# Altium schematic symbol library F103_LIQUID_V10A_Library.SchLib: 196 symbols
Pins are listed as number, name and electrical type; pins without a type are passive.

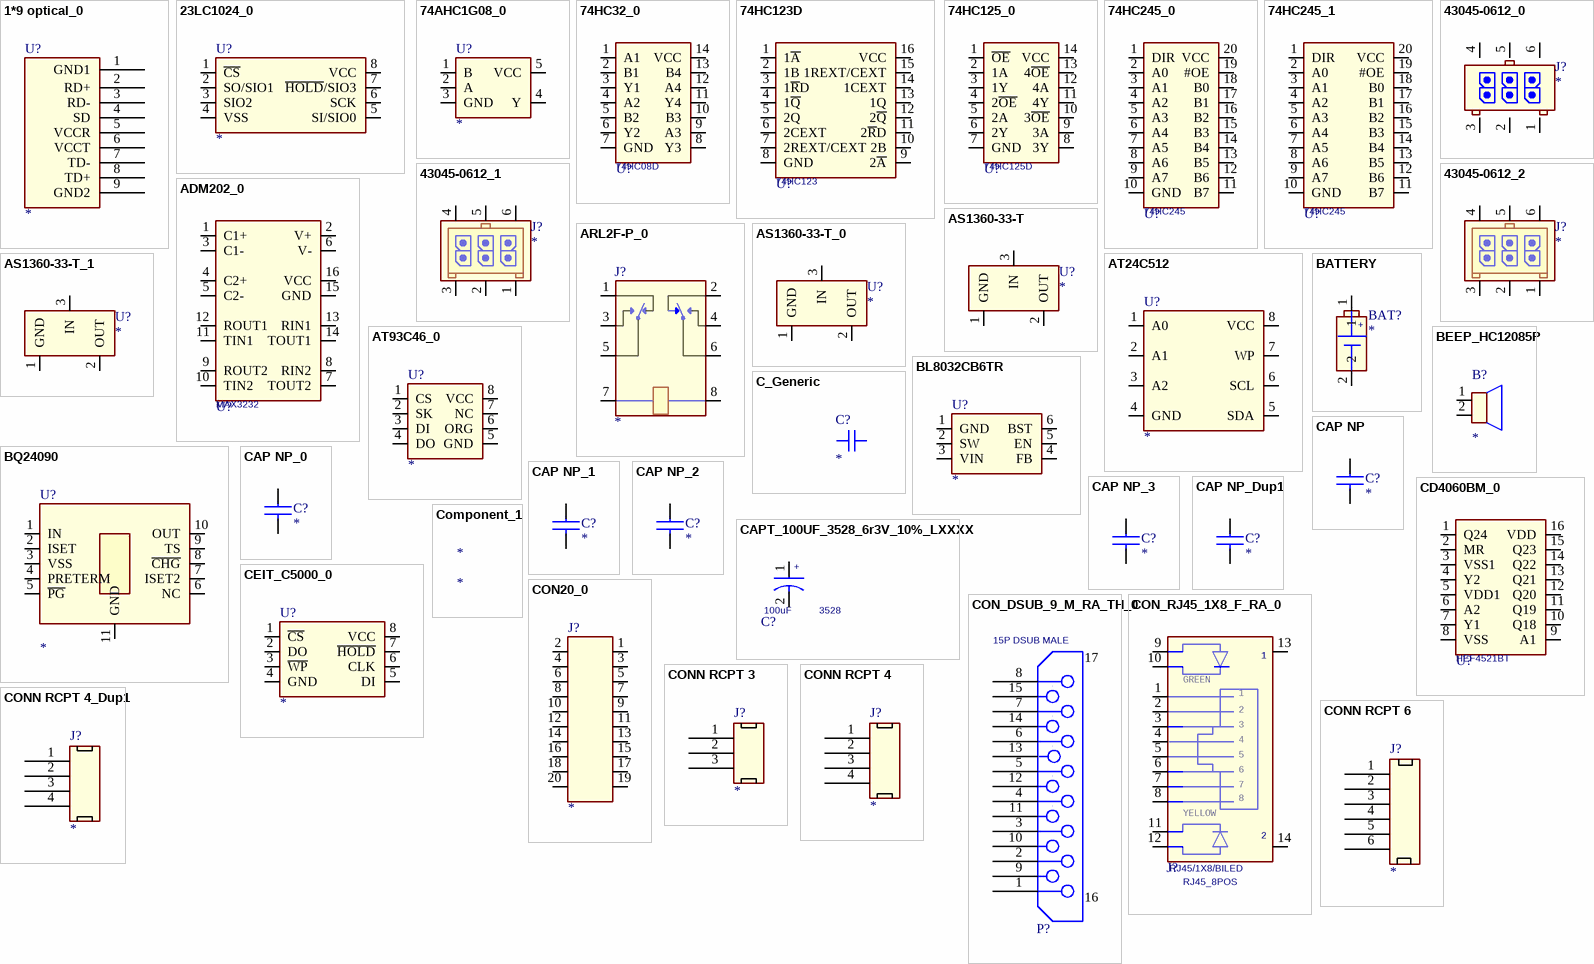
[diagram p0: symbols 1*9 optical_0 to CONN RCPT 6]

## 1*9 optical_0
designator U?
Optical Transceiver
footprint 1*9 optical
pins: 1 GND1, 2 RD+, 3 RD-, 4 SD, 5 VCCR, 6 VCCT, 7 TD-, 8 TD+, 9 GND2

## 23LC1024_0
designator U?
footprint SO8
pins: 1 ~{CS}, 2 SO/SIO1, 3 SIO2, 4 VSS, 5 SI/SIO0, 6 SCK, 7 ~{HOLD}/SIO3, 8 VCC

## 74AHC1G08_0
designator U?
Single 2-Input Positive-AND Gate; Corporation: TI
footprint SOT23-5
pins: 1 B, 2 A, 3 GND, 4 Y, 5 VCC

## 74HC32_0
designator U?, comment 74HC08D
Quad 2-input AND gate; Corporation: NXP
footprint sop14
pins: 1 A1, 2 B1, 3 Y1, 4 A2, 5 B2, 6 Y2, 7 GND, 8 Y3, 9 A3, 10 B3, 11 Y4, 12 A4, 13 B4, 14 VCC

## 74HC123D
designator U?, comment 74HC123
Dual retriggerable monostable multivibrator with reset; Corporation: NXP
footprint SOIC16
pins: 1 1~{A}, 2 1B, 3 1~{R}D, 4 1~{Q}, 5 2Q, 6 2CEXT, 7 2REXT/CEXT, 8 GND, 9 2~{A}, 10 2B, 11 2~{R}D, 12 2~{Q}, 13 1Q, 14 1CEXT, 15 1REXT/CEXT, 16 VCC

## 74HC125_0
designator U?, comment 74HC125D
Quad buffer line driver; Corporation: NXP
pins: 1 ~{OE}, 2 1A, 3 1Y, 4 2~{OE}, 5 2A, 6 2Y, 7 GND, 8 3Y, 9 3A, 10 3~{OE}, 11 4Y, 12 4A, 13 4~{OE}, 14 VCC

## 74HC245_0
designator U?, comment 74HC245
pins: 1 DIR, 2 A0, 3 A1, 4 A2, 5 A3, 6 A4, 7 A5, 8 A6, 9 A7, 10 GND, 11 B7, 12 B6, 13 B5, 14 B4, 15 B3, 16 B2, 17 B1, 18 B0, 19 #OE, 20 VCC

## 74HC245_1
designator U?, comment 74HC245
Octal Bus Transceivers With 3-State Outputs; Corporation: TI
pins: 1 DIR, 2 A0, 3 A1, 4 A2, 5 A3, 6 A4, 7 A5, 8 A6, 9 A7, 10 GND, 11 B7, 12 B6, 13 B5, 14 B4, 15 B3, 16 B2, 17 B1, 18 B0, 19 #OE, 20 VCC

## 43045-0612_0
designator J?
footprint 43045-06
pins: 1, 2, 3, 4, 5, 6

## 43045-0612_1
designator J?
footprint 43045-06
pins: 1, 2, 3, 4, 5, 6

## 43045-0612_2
designator J?
Header,3mm,3x2,TH; Corporation: MOLEX
footprint 43045-06
pins: 1, 2, 3, 4, 5, 6

## ADM202_0
designator U?, comment MAX3232
pins: 1 C1+, 2 V+, 3 C1-, 4 C2+, 5 C2-, 6 V-, 7 TOUT2, 8 RIN2, 9 ROUT2, 10 TIN2, 11 TIN1, 12 ROUT1, 13 RIN1, 14 TOUT1, 15 GND, 16 VCC

## ARL2F-P_0
designator J?
RELAY; Corporatation: AIKS
footprint ARL2F-P
pins: 1, 2, 3, 4, 5, 6, 7, 8

## AS1360-33-T
designator U?
Corporation: austria micro systems
footprint SOT23_123
pins: 1 GND, 2 OUT, 3 IN

## AS1360-33-T_0
designator U?
Corporation: TOREX
footprint SOT23_123
pins: 1 GND, 2 OUT, 3 IN

## AS1360-33-T_1
designator U?
1.5μA Low-Power,Positive Voltage Regulator; Corporation: Austria Micro Systems
footprint SOT23_123
pins: 1 GND, 2 OUT, 3 IN

## AT24C512
designator U?
footprint SOIC8
pins: 1 A0, 2 A1, 3 A2, 4 GND, 5 SDA, 6 SCL, 7 WP, 8 VCC

## AT93C46_0
designator U?
pins: 1 CS, 2 SK, 3 DI, 4 DO, 5 GND, 6 ORG, 7 NC, 8 VCC

## BATTERY
designator BAT?
footprint BATTERY
pins: 1, 2

## BEEP_HC12085P
designator B?
footprint HC12085P
pins: 1 P, 2 G

## BL8032CB6TR
designator U?
500KHz, 18V, 2A Synchronous Step-Down Converter; Corporation: BELLING
footprint SOT23-6
pins: 1 GND, 2 SW, 3 VIN, 4 FB, 5 EN, 6 BST

## BQ24090
designator U?
1A, Single-Input, Single Cell Li-Ion and Li-Pol Battery Charger; Corporation: TI
footprint HVSSOP-10
pins: 1 IN, 2 ISET, 3 VSS, 4 PRETERM, 5 ~{PG}, 6 NC, 7 ISET2, 8 ~{CHG}, 9 TS, 10 OUT, 11 GND

## C_Generic
designator C?
pins: 1, 2

## CAP NP
designator C?
pins: 1, 2

## CAP NP_0
designator C?
Corporation: FH
pins: 1, 2

## CAP NP_1
designator C?
CAP,CERM,0.1uF,50V,+/-10%,X7R,0603; Corporation: FH
pins: 1, 2

## CAP NP_2
designator C?
CAP,CERM,0.1uF,50V,+/-10%,X7R,0603; Corporation: FH
pins: 1, 2

## CAP NP_3
designator C?
CAP,CERM,0.1uF,50V,+/-10%,X7R,0603; Corporation: FH
pins: 1, 2

## CAP NP_Dup1
designator C?
pins: 1, 2

## CAPT_100UF_3528_6r3V_10%_LXXXX
designator C?, comment 100uF  Shape: 3528
GRN: LHR; EP#: P10100000000041; MFGI 2#: KEM: T494B107K006ATH; MFGI 1#: AVX: TPSB107K006R; Type: LESR
footprint CT_3528_IPC
pins: 1, 2
1 alternate drawing of the same symbol

## CD4060BM_0
designator U?, comment HEF4521BT
24-stage frequency divider and oscillator; Corporation: NXP
footprint SOP16
pins: 1 Q24, 2 MR, 3 VSS1, 4 Y2, 5 VDD1, 6 A2, 7 Y1, 8 VSS, 9 A1, 10 Q18, 11 Q19, 12 Q20, 13 Q21, 14 Q22, 15 Q23, 16 VDD

## CEIT_C5000_0
designator U?
128M-BIT SERIAL FLASH MEMORY; Corporation: winbond
footprint SO8
pins: 1 ~{CS}, 2 DO, 3 ~{WP}, 4 GND, 5 DI, 6 CLK, 7 ~{HOLD}, 8 VCC

## Component_1
designator *

## CON20_0
designator J?
Header,100mil,10x2,TH; Corporation: NEXTRON
pins: 1, 2, 3, 4, 5, 6, 7, 8, 9, 10, 11, 12, 13, 14, 15, 16, 17, 18, 19, 20

## CON_DSUB_9_M_RA_TH_0
designator P?, comment 15P DSUB MALE
DB15; Corporation: NEXTRON; MFG 1#: NOR: 182-009-112-171; Shape: .318-EDGE .109-HOLE; MFG 2#: MOL: 87203-6043; GRN: LHR; EP#: NA
footprint 87203-6043
pins: 1, 2, 3, 4, 5, 6, 7, 8, 9, 10, 11, 12, 13, 14, 15, 16 MT1, 17 MT2

## CON_RJ45_1X8_F_RA_0
designator J?, comment RJ45/1X8/BILED  SHAPE: RJ45_8POS
MFGI 1#: Tyco: 1116075-8; MFG 2#: Amphenol: RJHS-538A; CETEC: 1116075-8   or  RJHS538A; MFG 3#: Xmultiple:  XRJ-S-01-B-0-8-F2
footprint RJ45_8POS
pins: 1 TXP1, 2 TXN1, 3 RXP1, 4, 5, 6 RXN1, 7, 8, 9 R1_YC_GA, 10 R1_YA_GC, 11 L1_YC_GA, 12 L1_YA_GC, 13 EG2, 14 EG1

## CONN RCPT 3
designator J?
pins: 1, 2, 3

## CONN RCPT 4
designator J?
pins: 1, 2, 3, 4

## CONN RCPT 4_Dup1
designator J?
pins: 1, 2, 3, 4

## CONN RCPT 6
designator J?
pins: 1, 2, 3, 4, 5, 6

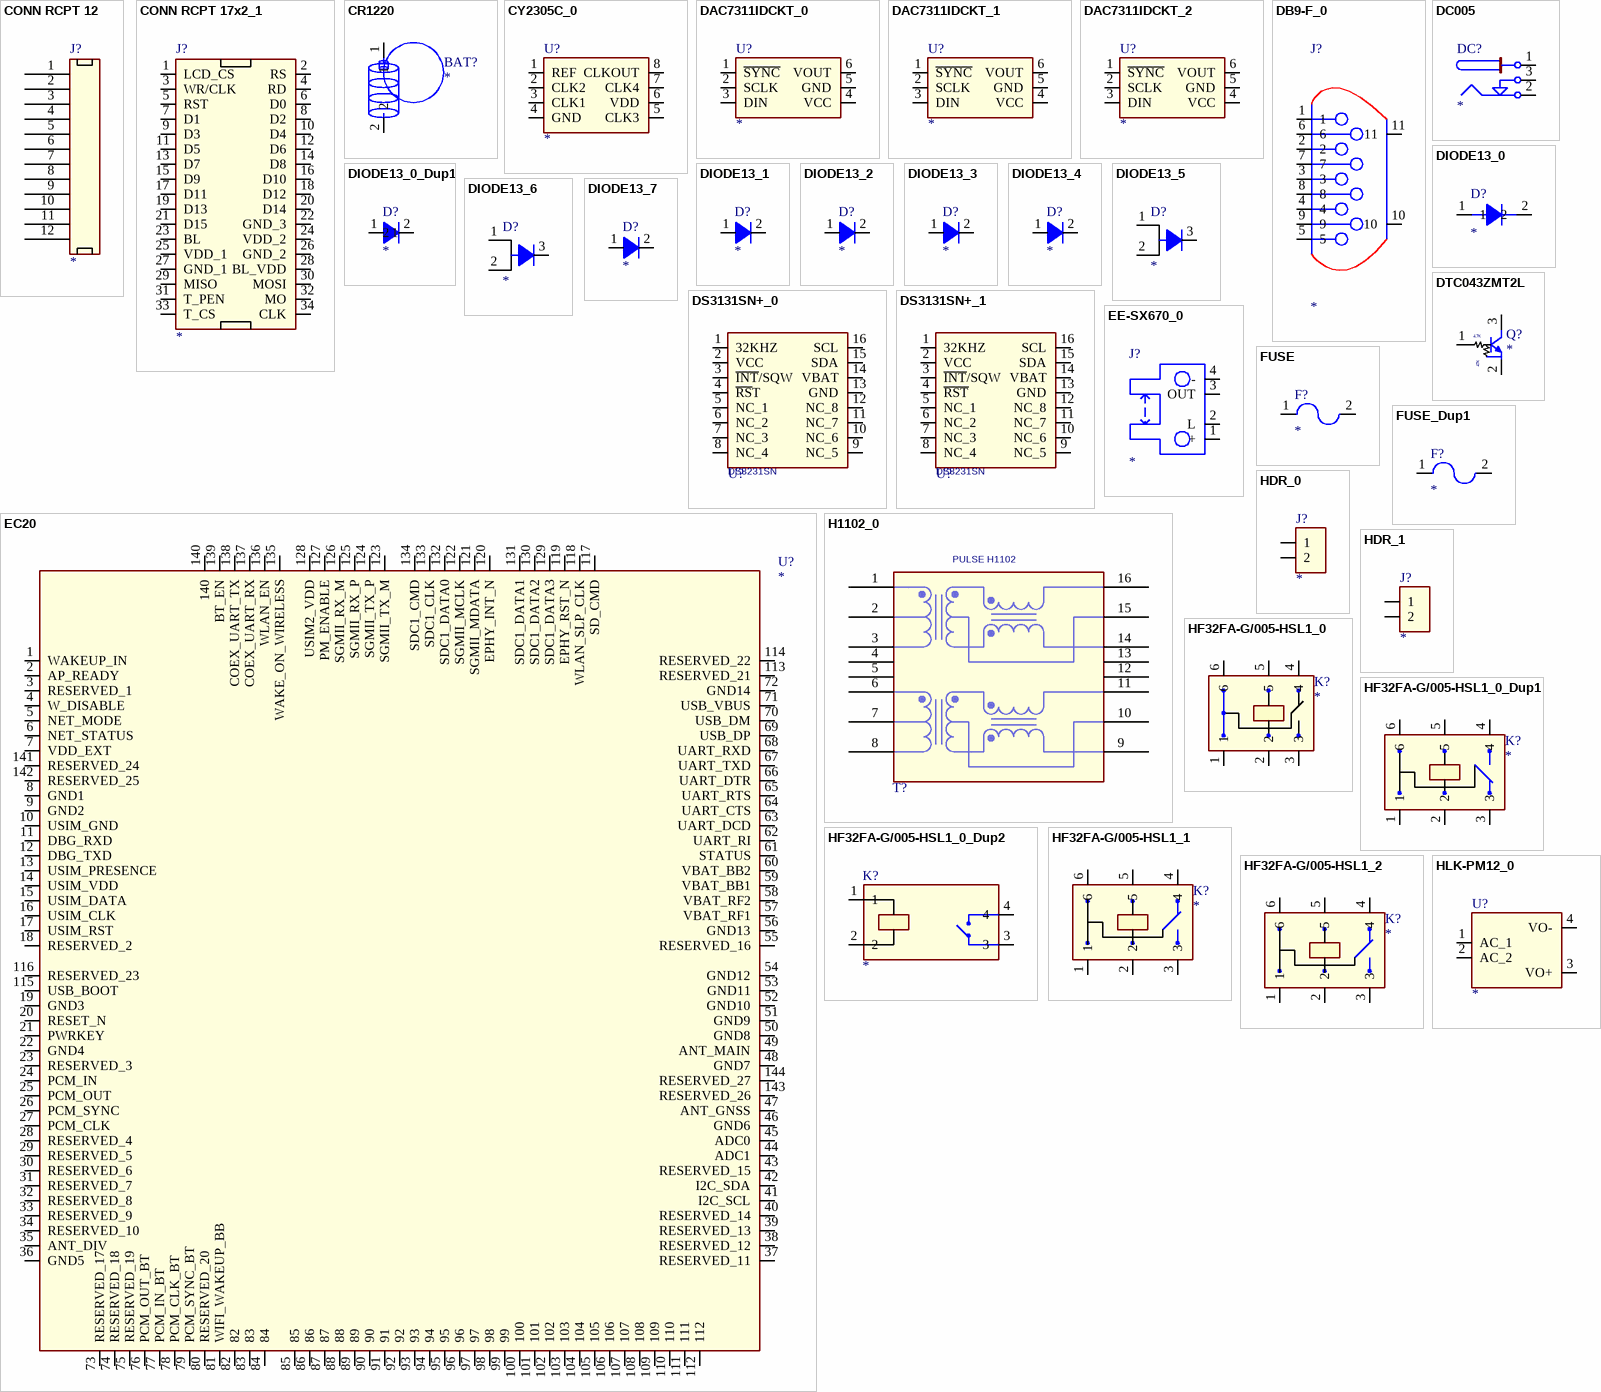
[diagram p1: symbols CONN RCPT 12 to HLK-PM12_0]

## CONN RCPT 12
designator J?
pins: 1, 2, 3, 4, 5, 6, 7, 8, 9, 10, 11, 12

## CONN RCPT 17x2_1
designator J?
pins: 1 LCD_CS, 2 RS, 3 WR/CLK, 4 RD, 5 RST, 6 D0, 7 D1, 8 D2, 9 D3, 10 D4, 11 D5, 12 D6, 13 D7, 14 D8, 15 D9, 16 D10, 17 D11, 18 D12, 19 D13, 20 D14, 21 D15, 22 GND_3, 23 BL, 24 VDD_2, 25 VDD_1, 26 GND_2, 27 GND_1, 28 BL_VDD, 29 MISO, 30 MOSI, 31 T_PEN, 32 MO, 33 T_CS, 34 CLK

## CR1220
designator BAT?
CR1220 Battery Holder
footprint CR1220
pins: 1, 2

## CY2305C_0
designator U?
Low Cost 3.3 V Zero Delay Buffer; Corporation: CYPRESS
footprint SOIC8
pins: 1 REF, 2 CLK2, 3 CLK1, 4 GND, 5 CLK3, 6 VDD, 7 CLK4, 8 CLKOUT

## DAC7311IDCKT_0
designator U?
Corporation: TI
pins: 1 ~{SYNC}, 2 SCLK, 3 DIN, 4 VCC, 5 GND, 6 VOUT

## DAC7311IDCKT_1
designator U?
Corporation: TI
footprint R-PDSO-G6
pins: 1 ~{SYNC}, 2 SCLK, 3 DIN, 4 VCC, 5 GND, 6 VOUT

## DAC7311IDCKT_2
designator U?
Digital-to-Analog Converters; Corporation: TI
footprint R-PDSO-G6
pins: 1 ~{SYNC}, 2 SCLK, 3 DIN, 4 VCC, 5 GND, 6 VOUT

## DB9-F_0
designator J?
DB9; Corporation: NEXTRON
footprint DB9-F
pins: 1, 2, 3, 4, 5, 6, 7, 8, 9, 10, 11

## DC005
designator DC?
footprint DC005
pins: 1, 2, 3

## DIODE13_0
designator D?
pins: 1, 2

## DIODE13_0_Dup1
designator D?
pins: 1, 2

## DIODE13_1
designator D?
pins: 1 ANODE, 2 CATHODE

## DIODE13_2
designator D?
pins: 1 ANODE, 2 CATHODE

## DIODE13_3
designator D?
Corporation: ROHM
pins: 1 ANODE, 2 CATHODE

## DIODE13_4
designator D?
Corporation: VISHAY
pins: 1 ANODE, 2 CATHODE

## DIODE13_5
designator D?
Corporation: VISHAY
pins: 1 ANODE, 2 CATHODE, 3 CATHODE

## DIODE13_6
designator D?
Corporation: VISHAY
pins: 1 ANODE_1, 2 ANODE_2, 3 CATHODE

## DIODE13_7
designator D?
Diode,Switching,100 V,1A,0805F; Corporation: ROHM
pins: 1 ANODE, 2 CATHODE

## DS3131SN+_0
designator U?, comment DS3231SN
footprint SOIC16W
pins: 1 32KHZ, 2 VCC, 3 ~{INT}/SQW, 4 ~{RS}T, 5 NC_1, 6 NC_2, 7 NC_3, 8 NC_4, 9 NC_5, 10 NC_6, 11 NC_7, 12 NC_8, 13 GND, 14 VBAT, 15 SDA, 16 SCL

## DS3131SN+_1
designator U?, comment DS3231SN
Extremely Accurate I2C-Integrated RTC; Corporation: MAXIM
footprint SOIC16W
pins: 1 32KHZ, 2 VCC, 3 ~{INT}/SQW, 4 ~{RST}, 5 NC_1, 6 NC_2, 7 NC_3, 8 NC_4, 9 NC_5, 10 NC_6, 11 NC_7, 12 NC_8, 13 GND, 14 VBAT, 15 SDA, 16 SCL

## DTC043ZMT2L
designator Q?
DTC043ZMT2L; Type: NPN; Corporation: ROHM
footprint SOT-723
pins: 1, 2, 3

## EC20
designator U?
4G LTE MODULE; Corporation: MEIG
footprint MEIG
pins: 1 WAKEUP_IN, 2 AP_READY, 3 RESERVED_1, 4 W_DISABLE, 5 NET_MODE, 6 NET_STATUS, 7 VDD_EXT, 8 GND1, 9 GND2, 10 USIM_GND, 11 DBG_RXD, 12 DBG_TXD, 13 USIM_PRESENCE, 14 USIM_VDD, 15 USIM_DATA, 16 USIM_CLK, 17 USIM_RST, 18 RESERVED_2, 19 GND3, 20 RESET_N, 21 PWRKEY, 22 GND4, 23 RESERVED_3, 24 PCM_IN, 25 PCM_OUT, 26 PCM_SYNC, 27 PCM_CLK, 28 RESERVED_4, 29 RESERVED_5, 30 RESERVED_6, 31 RESERVED_7, 32 RESERVED_8, 33 RESERVED_9, 34 RESERVED_10, 35 ANT_DIV, 36 GND5, 37 RESERVED_11, 38 RESERVED_12, 39 RESERVED_13, 40 RESERVED_14, 41 I2C_SCL, 42 I2C_SDA, 43 RESERVED_15, 44 ADC1, 45 ADC0, 46 GND6, 47 ANT_GNSS, 48 GND7, 49 ANT_MAIN, 50 GND8, 51 GND9, 52 GND10, 53 GND11, 54 GND12, 55 RESERVED_16, 56 GND13, 57 VBAT_RF1, 58 VBAT_RF2, 59 VBAT_BB1, 60 VBAT_BB2, 61 STATUS, 62 UART_RI, 63 UART_DCD, 64 UART_CTS, 65 UART_RTS, 66 UART_DTR, 67 UART_TXD, 68 UART_RXD, 69 USB_DP, 70 USB_DM, 71 USB_VBUS, 72 GND14, 73 RESERVED_17, 74 RESERVED_18, 75 RESERVED_19, 76 PCM_OUT_BT, 77 PCM_IN_BT, 78 PCM_CLK_BT, 79 PCM_SYNC_BT, 80 RESERVED_20, 81 WIFI_WAKEUP_BB, 82, 83, 84, 85, 86, 87, 88, 89, 90, 91, 92, 93, 94, 95, 96, 97, 98, 99, 100, 101, 102, 103, 104, 105, 106, 107, 108, 109, 110, 111, 112, 113 RESERVED_21, 114 RESERVED_22, 115 USB_BOOT, 116 RESERVED_23, 117 SD_CMD, 118 WLAN_SLP_CLK, 119 EPHY_RST_N, 120 EPHY_INT_N, 121 SGMII_MDATA, 122 SGMII_MCLK, 123 SGMII_TX_M, 124 SGMII_TX_P, 125 SGMII_RX_P, 126 SGMII_RX_M, 127 PM_ENABLE, 128 USIM2_VDD, 129 SDC1_DATA3, 130 SDC1_DATA2, 131 SDC1_DATA1, 132 SDC1_DATA0, 133 SDC1_CLK, 134 SDC1_CMD, 135 WAKE_ON_WIRELESS, 136 WLAN_EN, 137 COEX_UART_RX, 138 COEX_UART_TX, 139 BT_EN, 140, 141 RESERVED_24, 142 RESERVED_25, 143 RESERVED_26, 144 RESERVED_27

## EE-SX670_0
designator J?
Header,2.54mm,4x1,TH
footprint EE-SX670
pins: 1 +, 2 L, 3 OUT, 4 -

## FUSE
designator F?
footprint SMD-2920
pins: 1, 2

## FUSE_Dup1
designator F?
footprint SMD-2920
pins: 1, 2

## H1102_0
designator T?, comment PULSE H1102
MFGI 2#: XFMRS: XFATM9BIT; MFGI 1#: Pulse: HX1188; MFG 2#: BelFuse: S558- 5999-T7; MFG 1#: Pulse: H1102; SHAPE: H1102-SMT
pins: 1, 2, 3, 4, 5, 6, 7, 8, 9, 10, 11, 12, 13, 14, 15, 16

## HDR_0
designator J?
pins: 1, 2

## HDR_1
designator J?
Header,2.54mm,2x1,TH; Corporation: NEXTRON
pins: 1, 2

## HF32FA-G/005-HSL1_0
designator K?
SPST; Corporation: HF
footprint HF32FA-G/005-HSL1
pins: 1, 2, 3, 4, 5, 6

## HF32FA-G/005-HSL1_0_Dup1
designator K?
SPST; Corporation: HF
footprint HF32FA-G/005-HSL1
pins: 1, 2, 3, 4, 5, 6

## HF32FA-G/005-HSL1_0_Dup2
designator K?
SPST; Corporation: HF
footprint HF32FA-G/005-HSL1
pins: 1, 2, 3, 4

## HF32FA-G/005-HSL1_1
designator K?
SPST; Corporation: HF
footprint HF32FA-G/005-HSL1
pins: 1, 2, 3, 4, 5, 6

## HF32FA-G/005-HSL1_2
designator K?
SPST; Corporation: HF
footprint HF32FA-G/005-HSL1
pins: 1, 2, 3, 4, 5, 6

## HLK-PM12_0
designator U?
ACDC MODULA; Corporation: HI-LINK
footprint HLK-PM12
pins: 1 AC_1, 2 AC_2, 3 VO+, 4 VO-

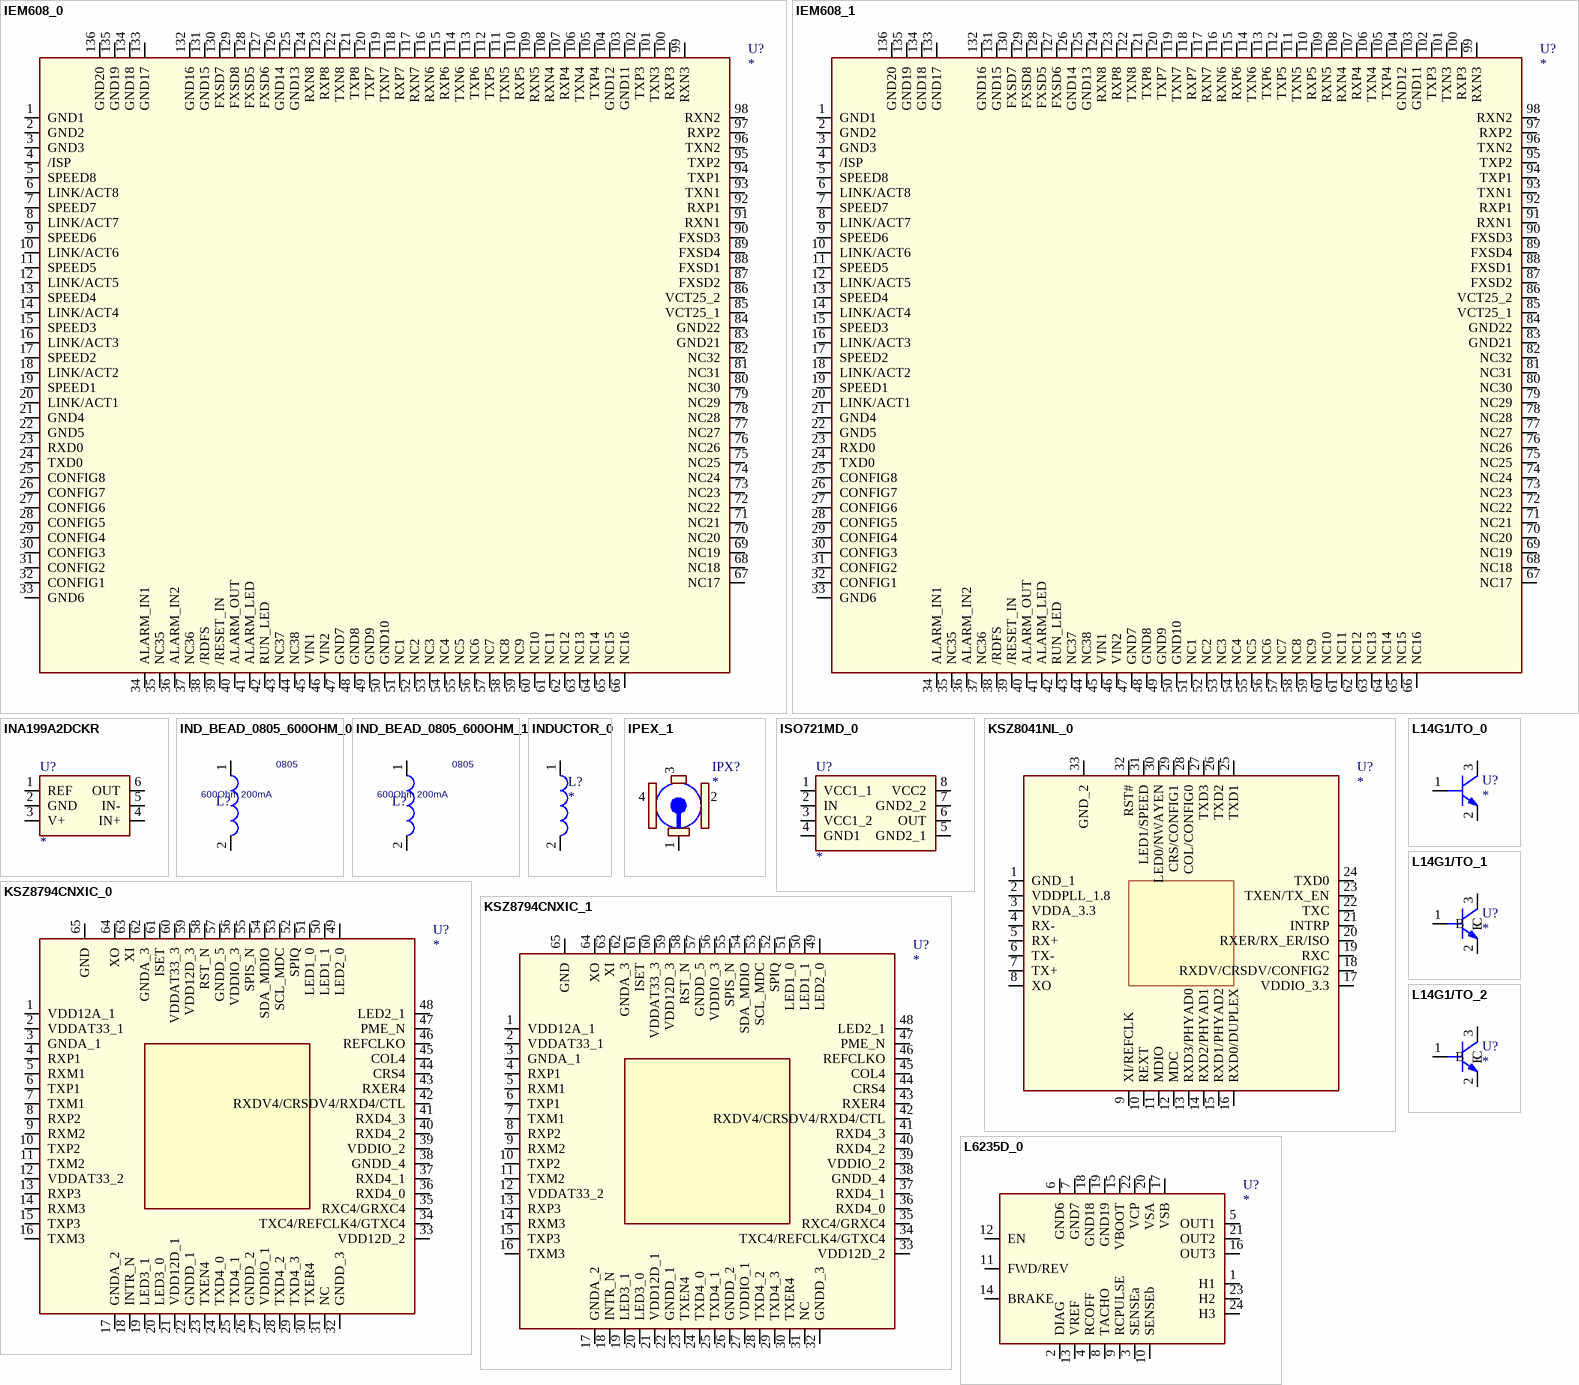
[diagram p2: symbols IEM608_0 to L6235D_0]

## IEM608_0
designator U?
footprint IEM608
pins: 1 GND1, 2 GND2, 3 GND3, 4 /ISP, 5 SPEED8, 6 LINK/ACT8, 7 SPEED7, 8 LINK/ACT7, 9 SPEED6, 10 LINK/ACT6, 11 SPEED5, 12 LINK/ACT5, 13 SPEED4, 14 LINK/ACT4, 15 SPEED3, 16 LINK/ACT3, 17 SPEED2, 18 LINK/ACT2, 19 SPEED1, 20 LINK/ACT1, 21 GND4, 22 GND5, 23 RXD0, 24 TXD0, 25 CONFIG8, 26 CONFIG7, 27 CONFIG6, 28 CONFIG5, 29 CONFIG4, 30 CONFIG3, 31 CONFIG2, 32 CONFIG1, 33 GND6, 34 ALARM_IN1, 35 NC35, 36 ALARM_IN2, 37 NC36, 38 /RDFS, 39 /RESET_IN, 40 ALARM_OUT, 41 ALARM_LED, 42 RUN_LED, 43 NC37, 44 NC38, 45 VIN1, 46 VIN2, 47 GND7, 48 GND8, 49 GND9, 50 GND10, 51 NC1, 52 NC2, 53 NC3, 54 NC4, 55 NC5, 56 NC6, 57 NC7, 58 NC8, 59 NC9, 60 NC10, 61 NC11, 62 NC12, 63 NC13, 64 NC14, 65 NC15, 66 NC16, 67 NC17, 68 NC18, 69 NC19, 70 NC20, 71 NC21, 72 NC22, 73 NC23, 74 NC24, 75 NC25, 76 NC26, 77 NC27, 78 NC28, 79 NC29, 80 NC30, 81 NC31, 82 NC32, 83 GND21, 84 GND22, 85 VCT25_1, 86 VCT25_2, 87 FXSD2, 88 FXSD1, 89 FXSD4, 90 FXSD3, 91 RXN1, 92 RXP1, 93 TXN1, 94 TXP1, 95 TXP2, 96 TXN2, 97 RXP2, 98 RXN2, 99 RXN3, 100 RXP3, 101 TXN3, 102 TXP3, 103 GND11, 104 GND12, 105 TXP4, 106 TXN4, 107 RXP4, 108 RXN4, 109 RXN5, 110 RXP5, 111 TXN5, 112 TXP5, 113 TXP6, 114 TXN6, 115 RXP6, 116 RXN6, 117 RXN7, 118 RXP7, 119 TXN7, 120 TXP7, 121 TXP8, 122 TXN8, 123 RXP8, 124 RXN8, 125 GND13, 126 GND14, 127 FXSD6, 128 FXSD5, 129 FXSD8, 130 FXSD7, 131 GND15, 132 GND16, 133 GND17, 134 GND18, 135 GND19, 136 GND20

## IEM608_1
designator U?
100M Industrial Ethernet module; Corporation: 3onedata
footprint IEM608
pins: 1 GND1, 2 GND2, 3 GND3, 4 /ISP, 5 SPEED8, 6 LINK/ACT8, 7 SPEED7, 8 LINK/ACT7, 9 SPEED6, 10 LINK/ACT6, 11 SPEED5, 12 LINK/ACT5, 13 SPEED4, 14 LINK/ACT4, 15 SPEED3, 16 LINK/ACT3, 17 SPEED2, 18 LINK/ACT2, 19 SPEED1, 20 LINK/ACT1, 21 GND4, 22 GND5, 23 RXD0, 24 TXD0, 25 CONFIG8, 26 CONFIG7, 27 CONFIG6, 28 CONFIG5, 29 CONFIG4, 30 CONFIG3, 31 CONFIG2, 32 CONFIG1, 33 GND6, 34 ALARM_IN1, 35 NC35, 36 ALARM_IN2, 37 NC36, 38 /RDFS, 39 /RESET_IN, 40 ALARM_OUT, 41 ALARM_LED, 42 RUN_LED, 43 NC37, 44 NC38, 45 VIN1, 46 VIN2, 47 GND7, 48 GND8, 49 GND9, 50 GND10, 51 NC1, 52 NC2, 53 NC3, 54 NC4, 55 NC5, 56 NC6, 57 NC7, 58 NC8, 59 NC9, 60 NC10, 61 NC11, 62 NC12, 63 NC13, 64 NC14, 65 NC15, 66 NC16, 67 NC17, 68 NC18, 69 NC19, 70 NC20, 71 NC21, 72 NC22, 73 NC23, 74 NC24, 75 NC25, 76 NC26, 77 NC27, 78 NC28, 79 NC29, 80 NC30, 81 NC31, 82 NC32, 83 GND21, 84 GND22, 85 VCT25_1, 86 VCT25_2, 87 FXSD2, 88 FXSD1, 89 FXSD4, 90 FXSD3, 91 RXN1, 92 RXP1, 93 TXN1, 94 TXP1, 95 TXP2, 96 TXN2, 97 RXP2, 98 RXN2, 99 RXN3, 100 RXP3, 101 TXN3, 102 TXP3, 103 GND11, 104 GND12, 105 TXP4, 106 TXN4, 107 RXP4, 108 RXN4, 109 RXN5, 110 RXP5, 111 TXN5, 112 TXP5, 113 TXP6, 114 TXN6, 115 RXP6, 116 RXN6, 117 RXN7, 118 RXP7, 119 TXN7, 120 TXP7, 121 TXP8, 122 TXN8, 123 RXP8, 124 RXN8, 125 GND13, 126 GND14, 127 FXSD6, 128 FXSD5, 129 FXSD8, 130 FXSD7, 131 GND15, 132 GND16, 133 GND17, 134 GND18, 135 GND19, 136 GND20

## INA199A2DCKR
designator U?
Current-Shunt Monitor; Corporation: TI
footprint SOT-363
pins: 1 REF, 2 GND, 3 V+, 4 IN+, 5 IN-, 6 OUT

## IND_BEAD_0805_600OHM_0
designator L?, comment 600Ohm 200mA  Shape: 0805
BEAD,60R/100MHz,6A,0805; Corporation: muRata; EPI#: P11000000000010; GRN: LHR; MFG 1#: MUR: BLM21B601SPT; MFG 2#: TDK: MMZ2012Y601B
footprint L_0805_IPC
pins: 1 A, 2 B
1 alternate drawing of the same symbol

## IND_BEAD_0805_600OHM_1
designator L?, comment 600Ohm 200mA  Shape: 0805
BEAD,60R/100MHz,6A,0805; Corporation: muRata; EPI#: P11000000000010; GRN: LHR; MFG 1#: MUR: BLM21B601SPT; MFG 2#: TDK: MMZ2012Y601B
footprint L_0805_IPC
pins: 1 A, 2 B
1 alternate drawing of the same symbol

## INDUCTOR_0
designator L?
pins: 1, 2

## IPEX_1
designator IPX?
footprint IPEX
pins: 1, 2, 3, 4

## ISO721MD_0
designator U?
Corporation: TI
footprint SOIC8
pins: 1 VCC1_1, 2 IN, 3 VCC1_2, 4 GND1, 5 GND2_1, 6 OUT, 7 GND2_2, 8 VCC2

## KSZ8041NL_0
designator U?
10Base-T/100Base-TX Physical Layer Transceiver; Corporation: MICREL
footprint MLF-32
pins: 1 GND_1, 2 VDDPLL_1.8, 3 VDDA_3.3, 4 RX-, 5 RX+, 6 TX-, 7 TX+, 8 XO, 9 XI/REFCLK, 10 REXT, 11 MDIO, 12 MDC, 13 RXD3/PHYAD0, 14 RXD2/PHYAD1, 15 RXD1/PHYAD2, 16 RXD0/DUPLEX, 17 VDDIO_3.3, 18 RXDV/CRSDV/CONFIG2, 19 RXC, 20 RXER/RX_ER/ISO, 21 INTRP, 22 TXC, 23 TXEN/TX_EN, 24 TXD0, 25 TXD1, 26 TXD2, 27 TXD3, 28 COL/CONFIG0, 29 CRS/CONFIG1, 30 LED0/NWAYEN, 31 LED1/SPEED, 32 RST#, 33 GND_2

## KSZ8794CNXIC_0
designator U?
footprint QFN-64
pins: 1 VDD12A_1, 2 VDDAT33_1, 3 GNDA_1, 4 RXP1, 5 RXM1, 6 TXP1, 7 TXM1, 8 RXP2, 9 RXM2, 10 TXP2, 11 TXM2, 12 VDDAT33_2, 13 RXP3, 14 RXM3, 15 TXP3, 16 TXM3, 17 GNDA_2, 18 INTR_N, 19 LED3_1, 20 LED3_0, 21 VDD12D_1, 22 GNDD_1, 23 TXEN4, 24 TXD4_0, 25 TXD4_1, 26 GNDD_2, 27 VDDIO_1, 28 TXD4_2, 29 TXD4_3, 30 TXER4, 31 NC, 32 GNDD_3, 33 VDD12D_2, 34 TXC4/REFCLK4/GTXC4, 35 RXC4/GRXC4, 36 RXD4_0, 37 RXD4_1, 38 GNDD_4, 39 VDDIO_2, 40 RXD4_2, 41 RXD4_3, 42 RXDV4/CRSDV4/RXD4/CTL, 43 RXER4, 44 CRS4, 45 COL4, 46 REFCLKO, 47 PME_N, 48 LED2_1, 49 LED2_0, 50 LED1_1, 51 LED1_0, 52 SPIQ, 53 SCL_MDC, 54 SDA_MDIO, 55 SPIS_N, 56 VDDIO_3, 57 GNDD_5, 58 RST_N, 59 VDD12D_3, 60 VDDAT33_3, 61 ISET, 62 GNDA_3, 63 XI, 64 XO, 65 GND

## KSZ8794CNXIC_1
designator U?
4-Port 10/100 Managed Ethernet Switch; Corporation: MIREL
footprint QFN-64
pins: 1 VDD12A_1, 2 VDDAT33_1, 3 GNDA_1, 4 RXP1, 5 RXM1, 6 TXP1, 7 TXM1, 8 RXP2, 9 RXM2, 10 TXP2, 11 TXM2, 12 VDDAT33_2, 13 RXP3, 14 RXM3, 15 TXP3, 16 TXM3, 17 GNDA_2, 18 INTR_N, 19 LED3_1, 20 LED3_0, 21 VDD12D_1, 22 GNDD_1, 23 TXEN4, 24 TXD4_0, 25 TXD4_1, 26 GNDD_2, 27 VDDIO_1, 28 TXD4_2, 29 TXD4_3, 30 TXER4, 31 NC, 32 GNDD_3, 33 VDD12D_2, 34 TXC4/REFCLK4/GTXC4, 35 RXC4/GRXC4, 36 RXD4_0, 37 RXD4_1, 38 GNDD_4, 39 VDDIO_2, 40 RXD4_2, 41 RXD4_3, 42 RXDV4/CRSDV4/RXD4/CTL, 43 RXER4, 44 CRS4, 45 COL4, 46 REFCLKO, 47 PME_N, 48 LED2_1, 49 LED2_0, 50 LED1_1, 51 LED1_0, 52 SPIQ, 53 SCL_MDC, 54 SDA_MDIO, 55 SPIS_N, 56 VDDIO_3, 57 GNDD_5, 58 RST_N, 59 VDD12D_3, 60 VDDAT33_3, 61 ISET, 62 GNDA_3, 63 XI, 64 XO, 65 GND

## L14G1/TO_0
designator U?
pins: 1 BASE, 2 EMITTER, 3 COLLECTOR

## L14G1/TO_1
designator U?
pins: 1 B, 2 E, 3 C

## L14G1/TO_2
designator U?
Transistor,PNP,45 V,0.5A,SOT23-3
pins: 1 B, 2 E, 3 C

## L6235D_0
designator U?
pins: 1 H1, 2 DIAG, 3 SENSEa, 4 RCOFF, 5 OUT1, 6 GND6, 7 GND7, 8 TACHO, 9 RCPULSE, 10 SENSEb, 11 FWD/REV, 12 EN, 13 VREF, 14 BRAKE, 15 VBOOT, 16 OUT3, 17 VSB, 18 GND18, 19 GND19, 20 VSA, 21 OUT2, 22 VCP, 23 H2, 24 H3

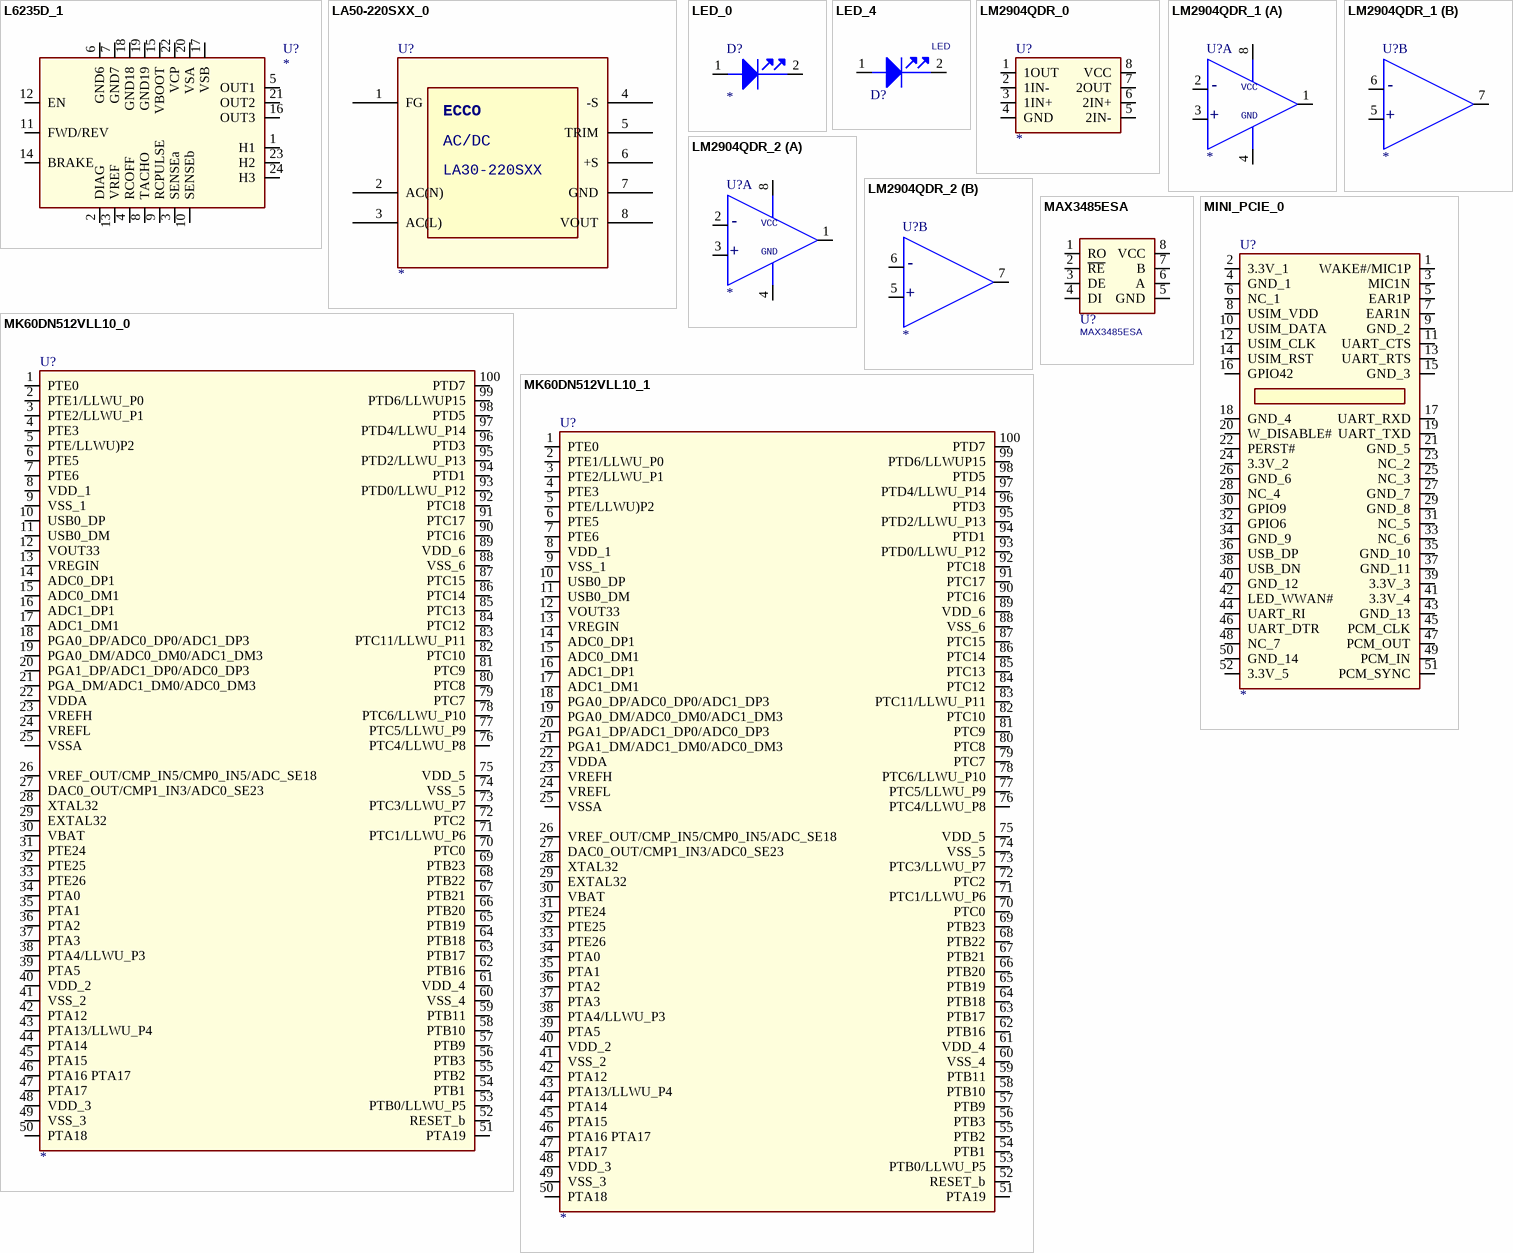
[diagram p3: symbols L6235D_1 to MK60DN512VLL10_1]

## L6235D_1
designator U?
Corporation: ST
pins: 1 H1, 2 DIAG, 3 SENSEa, 4 RCOFF, 5 OUT1, 6 GND6, 7 GND7, 8 TACHO, 9 RCPULSE, 10 SENSEb, 11 FWD/REV, 12 EN, 13 VREF, 14 BRAKE, 15 VBOOT, 16 OUT3, 17 VSB, 18 GND18, 19 GND19, 20 VSA, 21 OUT2, 22 VCP, 23 H2, 24 H3

## LA50-220SXX_0
designator U?
Corporation: ECCO
footprint LA50-220SXX
pins: 1 FG, 2 AC(N), 3 AC(L), 4 -S, 5 TRIM, 6 +S, 7 GND, 8 VOUT

## LED_0
designator D?
pins: 1 ANODE, 2 CATHODE

## LED_4
designator D?, comment LED
pins: 1 ANODE, 2 CATHODE

## LM2904QDR_0
designator U?
Corporation: TI
pins: 1 1OUT, 2 1IN-, 3 1IN+, 4 GND, 5 2IN-, 6 2IN+, 7 2OUT, 8 VCC

## LM2904QDR_1
designator U?
Dual Operational Amplifiers; Corporation: TI
footprint SOIC8
part A pins: 1 1OUT, 2 1IN-, 3 1IN+, 4 GND, 8 VCC
part B pins: 5 2IN+, 6 2IN-, 7 2OUT

## LM2904QDR_2
designator U?
Dual Operational Amplifiers; Corporation: TI
footprint SOIC8
part A pins: 1 1OUT, 2 1IN-, 3 1IN+, 4 GND, 8 VCC
part B pins: 5 2IN+, 6 2IN-, 7 2OUT

## MAX3485ESA
designator U?
pins: 1 RO, 2 ~{RE}, 3 DE, 4 DI, 5 GND, 6 A, 7 B, 8 VCC

## MINI_PCIE_0
designator U?
4G Wireless Module; Corporation: SIMCom
pins: 1 WAKE#/MIC1P, 2 3.3V_1, 3 MIC1N, 4 GND_1, 5 EAR1P, 6 NC_1, 7 EAR1N, 8 USIM_VDD, 9 GND_2, 10 USIM_DATA, 11 UART_CTS, 12 USIM_CLK, 13 UART_RTS, 14 USIM_RST, 15 GND_3, 16 GPIO42, 17 UART_RXD, 18 GND_4, 19 UART_TXD, 20 W_DISABLE#, 21 GND_5, 22 PERST#, 23 NC_2, 24 3.3V_2, 25 NC_3, 26 GND_6, 27 GND_7, 28 NC_4, 29 GND_8, 30 GPIO9, 31 NC_5, 32 GPIO6, 33 NC_6, 34 GND_9, 35 GND_10, 36 USB_DP, 37 GND_11, 38 USB_DN, 39 3.3V_3, 40 GND_12, 41 3.3V_4, 42 LED_WWAN#, 43 GND_13, 44 UART_RI, 45 PCM_CLK, 46 UART_DTR, 47 PCM_OUT, 48 NC_7, 49 PCM_IN, 50 GND_14, 51 PCM_SYNC, 52 3.3V_5

## MK60DN512VLL10_0
designator U?
footprint LQFP-100
pins: 1 PTE0, 2 PTE1/LLWU_P0, 3 PTE2/LLWU_P1, 4 PTE3, 5 PTE/LLWU)P2, 6 PTE5, 7 PTE6, 8 VDD_1, 9 VSS_1, 10 USB0_DP, 11 USB0_DM, 12 VOUT33, 13 VREGIN, 14 ADC0_DP1, 15 ADC0_DM1, 16 ADC1_DP1, 17 ADC1_DM1, 18 PGA0_DP/ADC0_DP0/ADC1_DP3, 19 PGA0_DM/ADC0_DM0/ADC1_DM3, 20 PGA1_DP/ADC1_DP0/ADC0_DP3, 21 PGA_DM/ADC1_DM0/ADC0_DM3, 22 VDDA, 23 VREFH, 24 VREFL, 25 VSSA, 26 VREF_OUT/CMP_IN5/CMP0_IN5/ADC_SE18, 27 DAC0_OUT/CMP1_IN3/ADC0_SE23, 28 XTAL32, 29 EXTAL32, 30 VBAT, 31 PTE24, 32 PTE25, 33 PTE26, 34 PTA0, 35 PTA1, 36 PTA2, 37 PTA3, 38 PTA4/LLWU_P3, 39 PTA5, 40 VDD_2, 41 VSS_2, 42 PTA12, 43 PTA13/LLWU_P4, 44 PTA14, 45 PTA15, 46 PTA16 PTA17, 47 PTA17, 48 VDD_3, 49 VSS_3, 50 PTA18, 51 PTA19, 52 RESET_b, 53 PTB0/LLWU_P5, 54 PTB1, 55 PTB2, 56 PTB3, 57 PTB9, 58 PTB10, 59 PTB11, 60 VSS_4, 61 VDD_4, 62 PTB16, 63 PTB17, 64 PTB18, 65 PTB19, 66 PTB20, 67 PTB21, 68 PTB22, 69 PTB23, 70 PTC0, 71 PTC1/LLWU_P6, 72 PTC2, 73 PTC3/LLWU_P7, 74 VSS_5, 75 VDD_5, 76 PTC4/LLWU_P8, 77 PTC5/LLWU_P9, 78 PTC6/LLWU_P10, 79 PTC7, 80 PTC8, 81 PTC9, 82 PTC10, 83 PTC11/LLWU_P11, 84 PTC12, 85 PTC13, 86 PTC14, 87 PTC15, 88 VSS_6, 89 VDD_6, 90 PTC16, 91 PTC17, 92 PTC18, 93 PTD0/LLWU_P12, 94 PTD1, 95 PTD2/LLWU_P13, 96 PTD3, 97 PTD4/LLWU_P14, 98 PTD5, 99 PTD6/LLWUP15, 100 PTD7

## MK60DN512VLL10_1
designator U?
footprint LQFP-100
pins: 1 PTE0, 2 PTE1/LLWU_P0, 3 PTE2/LLWU_P1, 4 PTE3, 5 PTE/LLWU)P2, 6 PTE5, 7 PTE6, 8 VDD_1, 9 VSS_1, 10 USB0_DP, 11 USB0_DM, 12 VOUT33, 13 VREGIN, 14 ADC0_DP1, 15 ADC0_DM1, 16 ADC1_DP1, 17 ADC1_DM1, 18 PGA0_DP/ADC0_DP0/ADC1_DP3, 19 PGA0_DM/ADC0_DM0/ADC1_DM3, 20 PGA1_DP/ADC1_DP0/ADC0_DP3, 21 PGA1_DM/ADC1_DM0/ADC0_DM3, 22 VDDA, 23 VREFH, 24 VREFL, 25 VSSA, 26 VREF_OUT/CMP_IN5/CMP0_IN5/ADC_SE18, 27 DAC0_OUT/CMP1_IN3/ADC0_SE23, 28 XTAL32, 29 EXTAL32, 30 VBAT, 31 PTE24, 32 PTE25, 33 PTE26, 34 PTA0, 35 PTA1, 36 PTA2, 37 PTA3, 38 PTA4/LLWU_P3, 39 PTA5, 40 VDD_2, 41 VSS_2, 42 PTA12, 43 PTA13/LLWU_P4, 44 PTA14, 45 PTA15, 46 PTA16 PTA17, 47 PTA17, 48 VDD_3, 49 VSS_3, 50 PTA18, 51 PTA19, 52 RESET_b, 53 PTB0/LLWU_P5, 54 PTB1, 55 PTB2, 56 PTB3, 57 PTB9, 58 PTB10, 59 PTB11, 60 VSS_4, 61 VDD_4, 62 PTB16, 63 PTB17, 64 PTB18, 65 PTB19, 66 PTB20, 67 PTB21, 68 PTB22, 69 PTB23, 70 PTC0, 71 PTC1/LLWU_P6, 72 PTC2, 73 PTC3/LLWU_P7, 74 VSS_5, 75 VDD_5, 76 PTC4/LLWU_P8, 77 PTC5/LLWU_P9, 78 PTC6/LLWU_P10, 79 PTC7, 80 PTC8, 81 PTC9, 82 PTC10, 83 PTC11/LLWU_P11, 84 PTC12, 85 PTC13, 86 PTC14, 87 PTC15, 88 VSS_6, 89 VDD_6, 90 PTC16, 91 PTC17, 92 PTC18, 93 PTD0/LLWU_P12, 94 PTD1, 95 PTD2/LLWU_P13, 96 PTD3, 97 PTD4/LLWU_P14, 98 PTD5, 99 PTD6/LLWUP15, 100 PTD7

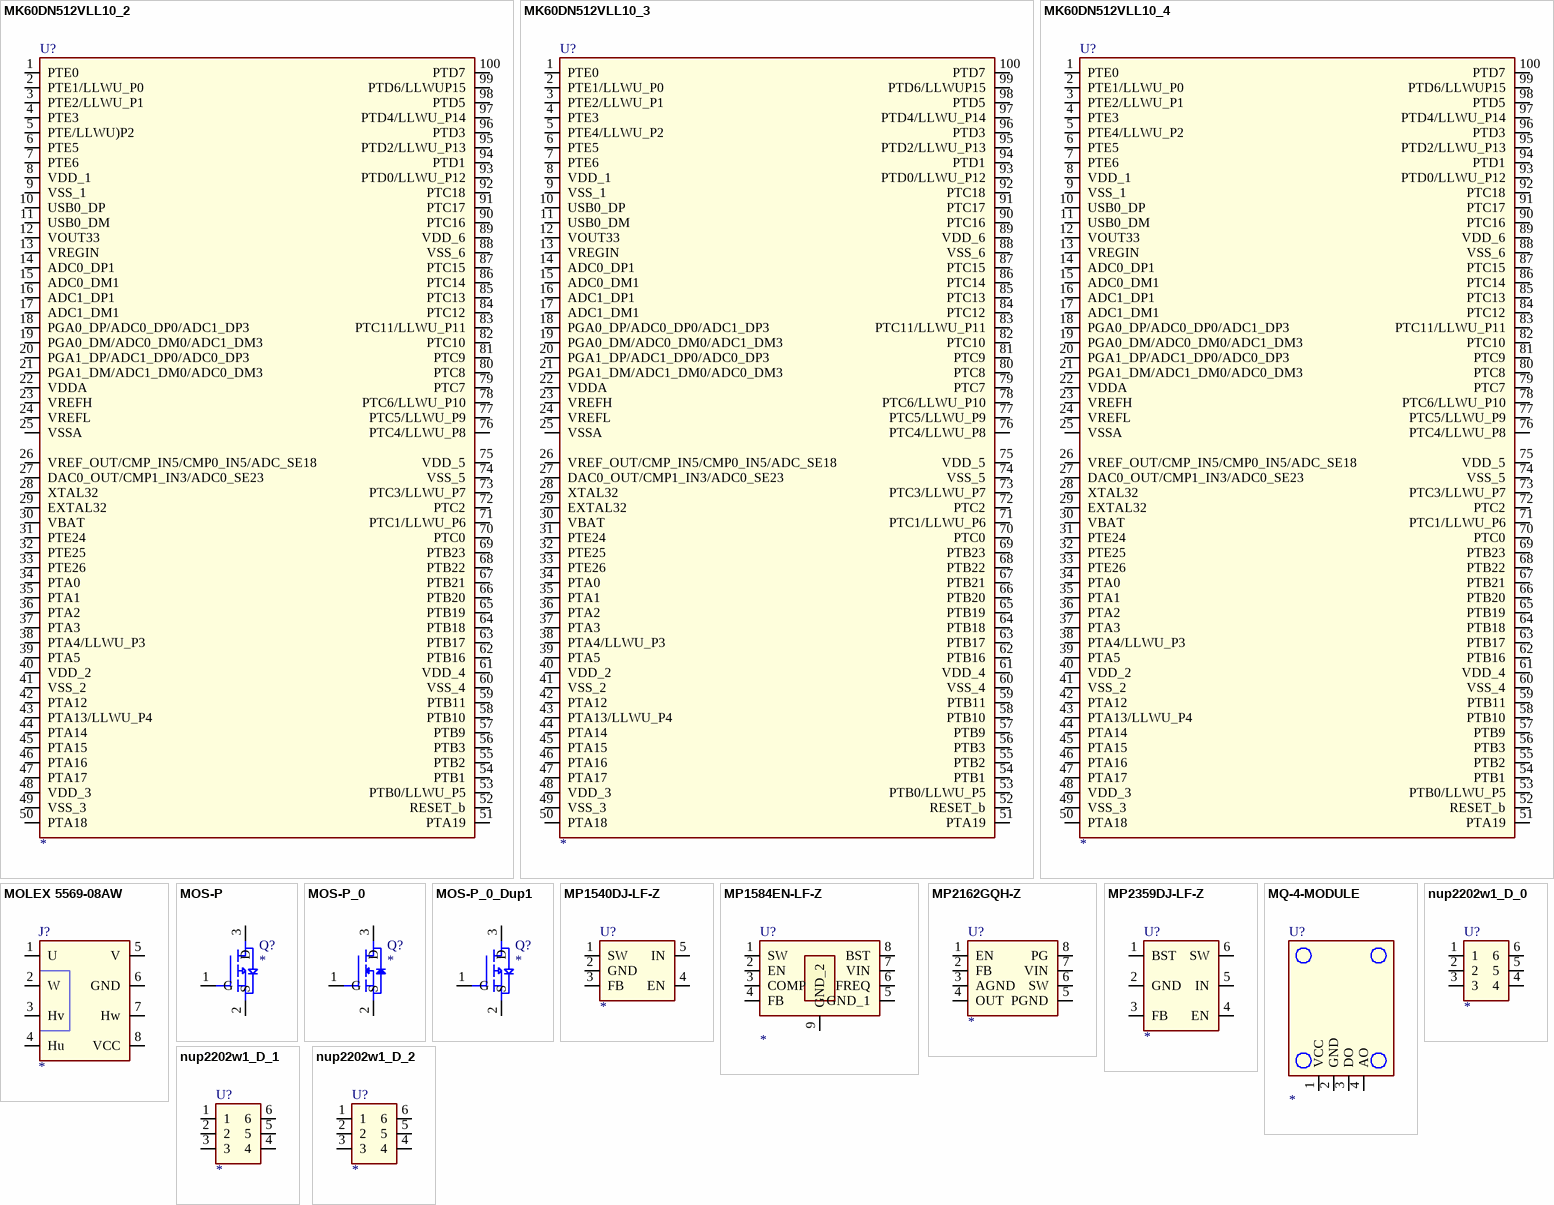
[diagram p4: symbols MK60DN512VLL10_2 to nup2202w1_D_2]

## MK60DN512VLL10_2
designator U?
footprint LQFP-100
pins: 1 PTE0, 2 PTE1/LLWU_P0, 3 PTE2/LLWU_P1, 4 PTE3, 5 PTE/LLWU)P2, 6 PTE5, 7 PTE6, 8 VDD_1, 9 VSS_1, 10 USB0_DP, 11 USB0_DM, 12 VOUT33, 13 VREGIN, 14 ADC0_DP1, 15 ADC0_DM1, 16 ADC1_DP1, 17 ADC1_DM1, 18 PGA0_DP/ADC0_DP0/ADC1_DP3, 19 PGA0_DM/ADC0_DM0/ADC1_DM3, 20 PGA1_DP/ADC1_DP0/ADC0_DP3, 21 PGA1_DM/ADC1_DM0/ADC0_DM3, 22 VDDA, 23 VREFH, 24 VREFL, 25 VSSA, 26 VREF_OUT/CMP_IN5/CMP0_IN5/ADC_SE18, 27 DAC0_OUT/CMP1_IN3/ADC0_SE23, 28 XTAL32, 29 EXTAL32, 30 VBAT, 31 PTE24, 32 PTE25, 33 PTE26, 34 PTA0, 35 PTA1, 36 PTA2, 37 PTA3, 38 PTA4/LLWU_P3, 39 PTA5, 40 VDD_2, 41 VSS_2, 42 PTA12, 43 PTA13/LLWU_P4, 44 PTA14, 45 PTA15, 46 PTA16, 47 PTA17, 48 VDD_3, 49 VSS_3, 50 PTA18, 51 PTA19, 52 RESET_b, 53 PTB0/LLWU_P5, 54 PTB1, 55 PTB2, 56 PTB3, 57 PTB9, 58 PTB10, 59 PTB11, 60 VSS_4, 61 VDD_4, 62 PTB16, 63 PTB17, 64 PTB18, 65 PTB19, 66 PTB20, 67 PTB21, 68 PTB22, 69 PTB23, 70 PTC0, 71 PTC1/LLWU_P6, 72 PTC2, 73 PTC3/LLWU_P7, 74 VSS_5, 75 VDD_5, 76 PTC4/LLWU_P8, 77 PTC5/LLWU_P9, 78 PTC6/LLWU_P10, 79 PTC7, 80 PTC8, 81 PTC9, 82 PTC10, 83 PTC11/LLWU_P11, 84 PTC12, 85 PTC13, 86 PTC14, 87 PTC15, 88 VSS_6, 89 VDD_6, 90 PTC16, 91 PTC17, 92 PTC18, 93 PTD0/LLWU_P12, 94 PTD1, 95 PTD2/LLWU_P13, 96 PTD3, 97 PTD4/LLWU_P14, 98 PTD5, 99 PTD6/LLWUP15, 100 PTD7

## MK60DN512VLL10_3
designator U?
footprint LQFP-100
pins: 1 PTE0, 2 PTE1/LLWU_P0, 3 PTE2/LLWU_P1, 4 PTE3, 5 PTE4/LLWU_P2, 6 PTE5, 7 PTE6, 8 VDD_1, 9 VSS_1, 10 USB0_DP, 11 USB0_DM, 12 VOUT33, 13 VREGIN, 14 ADC0_DP1, 15 ADC0_DM1, 16 ADC1_DP1, 17 ADC1_DM1, 18 PGA0_DP/ADC0_DP0/ADC1_DP3, 19 PGA0_DM/ADC0_DM0/ADC1_DM3, 20 PGA1_DP/ADC1_DP0/ADC0_DP3, 21 PGA1_DM/ADC1_DM0/ADC0_DM3, 22 VDDA, 23 VREFH, 24 VREFL, 25 VSSA, 26 VREF_OUT/CMP_IN5/CMP0_IN5/ADC_SE18, 27 DAC0_OUT/CMP1_IN3/ADC0_SE23, 28 XTAL32, 29 EXTAL32, 30 VBAT, 31 PTE24, 32 PTE25, 33 PTE26, 34 PTA0, 35 PTA1, 36 PTA2, 37 PTA3, 38 PTA4/LLWU_P3, 39 PTA5, 40 VDD_2, 41 VSS_2, 42 PTA12, 43 PTA13/LLWU_P4, 44 PTA14, 45 PTA15, 46 PTA16, 47 PTA17, 48 VDD_3, 49 VSS_3, 50 PTA18, 51 PTA19, 52 RESET_b, 53 PTB0/LLWU_P5, 54 PTB1, 55 PTB2, 56 PTB3, 57 PTB9, 58 PTB10, 59 PTB11, 60 VSS_4, 61 VDD_4, 62 PTB16, 63 PTB17, 64 PTB18, 65 PTB19, 66 PTB20, 67 PTB21, 68 PTB22, 69 PTB23, 70 PTC0, 71 PTC1/LLWU_P6, 72 PTC2, 73 PTC3/LLWU_P7, 74 VSS_5, 75 VDD_5, 76 PTC4/LLWU_P8, 77 PTC5/LLWU_P9, 78 PTC6/LLWU_P10, 79 PTC7, 80 PTC8, 81 PTC9, 82 PTC10, 83 PTC11/LLWU_P11, 84 PTC12, 85 PTC13, 86 PTC14, 87 PTC15, 88 VSS_6, 89 VDD_6, 90 PTC16, 91 PTC17, 92 PTC18, 93 PTD0/LLWU_P12, 94 PTD1, 95 PTD2/LLWU_P13, 96 PTD3, 97 PTD4/LLWU_P14, 98 PTD5, 99 PTD6/LLWUP15, 100 PTD7

## MK60DN512VLL10_4
designator U?
Kinetis K 32-bit MCU; Corporation: NXP
footprint LQFP-100
pins: 1 PTE0, 2 PTE1/LLWU_P0, 3 PTE2/LLWU_P1, 4 PTE3, 5 PTE4/LLWU_P2, 6 PTE5, 7 PTE6, 8 VDD_1, 9 VSS_1, 10 USB0_DP, 11 USB0_DM, 12 VOUT33, 13 VREGIN, 14 ADC0_DP1, 15 ADC0_DM1, 16 ADC1_DP1, 17 ADC1_DM1, 18 PGA0_DP/ADC0_DP0/ADC1_DP3, 19 PGA0_DM/ADC0_DM0/ADC1_DM3, 20 PGA1_DP/ADC1_DP0/ADC0_DP3, 21 PGA1_DM/ADC1_DM0/ADC0_DM3, 22 VDDA, 23 VREFH, 24 VREFL, 25 VSSA, 26 VREF_OUT/CMP_IN5/CMP0_IN5/ADC_SE18, 27 DAC0_OUT/CMP1_IN3/ADC0_SE23, 28 XTAL32, 29 EXTAL32, 30 VBAT, 31 PTE24, 32 PTE25, 33 PTE26, 34 PTA0, 35 PTA1, 36 PTA2, 37 PTA3, 38 PTA4/LLWU_P3, 39 PTA5, 40 VDD_2, 41 VSS_2, 42 PTA12, 43 PTA13/LLWU_P4, 44 PTA14, 45 PTA15, 46 PTA16, 47 PTA17, 48 VDD_3, 49 VSS_3, 50 PTA18, 51 PTA19, 52 RESET_b, 53 PTB0/LLWU_P5, 54 PTB1, 55 PTB2, 56 PTB3, 57 PTB9, 58 PTB10, 59 PTB11, 60 VSS_4, 61 VDD_4, 62 PTB16, 63 PTB17, 64 PTB18, 65 PTB19, 66 PTB20, 67 PTB21, 68 PTB22, 69 PTB23, 70 PTC0, 71 PTC1/LLWU_P6, 72 PTC2, 73 PTC3/LLWU_P7, 74 VSS_5, 75 VDD_5, 76 PTC4/LLWU_P8, 77 PTC5/LLWU_P9, 78 PTC6/LLWU_P10, 79 PTC7, 80 PTC8, 81 PTC9, 82 PTC10, 83 PTC11/LLWU_P11, 84 PTC12, 85 PTC13, 86 PTC14, 87 PTC15, 88 VSS_6, 89 VDD_6, 90 PTC16, 91 PTC17, 92 PTC18, 93 PTD0/LLWU_P12, 94 PTD1, 95 PTD2/LLWU_P13, 96 PTD3, 97 PTD4/LLWU_P14, 98 PTD5, 99 PTD6/LLWUP15, 100 PTD7

## MOLEX 5569-08AW
designator J?
footprint MOLEX_5569_8P
pins: 1 U, 2 W, 3 Hv, 4 Hu, 5 V, 6 GND, 7 Hw, 8 VCC

## MOS-P
designator Q?
footprint SOT23_GSD
pins: 1 G, 2 S, 3 D

## MOS-P_0
designator Q?
MOSFET,P,20V,-3.9A,SOT23-3; Corporation: VISHAY
footprint SOT23_GSD
pins: 1 G, 2 S, 3 D

## MOS-P_0_Dup1
designator Q?
MOSFET,P,20V,-3.9A,SOT23-3; Corporation: VISHAY
footprint SOT23_GSD
pins: 1 G, 2 S, 3 D

## MP1540DJ-LF-Z
designator U?
1.3MHz, 18V STEP-UP CONVERTER; Corporation: MPS
footprint TSOT23-5
pins: 1 SW, 2 GND, 3 FB, 4 EN, 5 IN

## MP1584EN-LF-Z
designator U?
3A, 1.5MHz, 28V Step-Down Converter; Corporation: MPS
footprint SOIC8-PAD
pins: 1 SW, 2 EN, 3 COMP, 4 FB, 5 GND_1, 6 FREQ, 7 VIN, 8 BST, 9 GND_2

## MP2162GQH-Z
designator U?
2A, 6V, 1.5MHz SYNCHRONOUS STEP-DOWN SWITCHER; Corporation: MPS
footprint QFN-8
pins: 1 EN, 2 FB, 3 AGND, 4 OUT, 5 PGND, 6 SW, 7 VIN, 8 PG

## MP2359DJ-LF-Z
designator U?
1.2A, 24V, 1.4MHz Step-Down Converter in a TSOT23-6; Corporation: MPS
footprint TSOT23-6
pins: 1 BST, 2 GND, 3 FB, 4 EN, 5 IN, 6 SW

## MQ-4-MODULE
designator U?
MQ-4-MODULE; Corporation: WINSEN
footprint MQ-4-MODULE
pins: 1 VCC, 2 GND, 3 DO, 4 AO

## nup2202w1_D_0
designator U?
footprint nup2202w
pins: 1, 2, 3, 4, 5, 6

## nup2202w1_D_1
designator U?
footprint nup2202w
pins: 1, 2, 3, 4, 5, 6

## nup2202w1_D_2
designator U?
TVS?Array; Corporation: ON
footprint nup2202w
pins: 1, 2, 3, 4, 5, 6

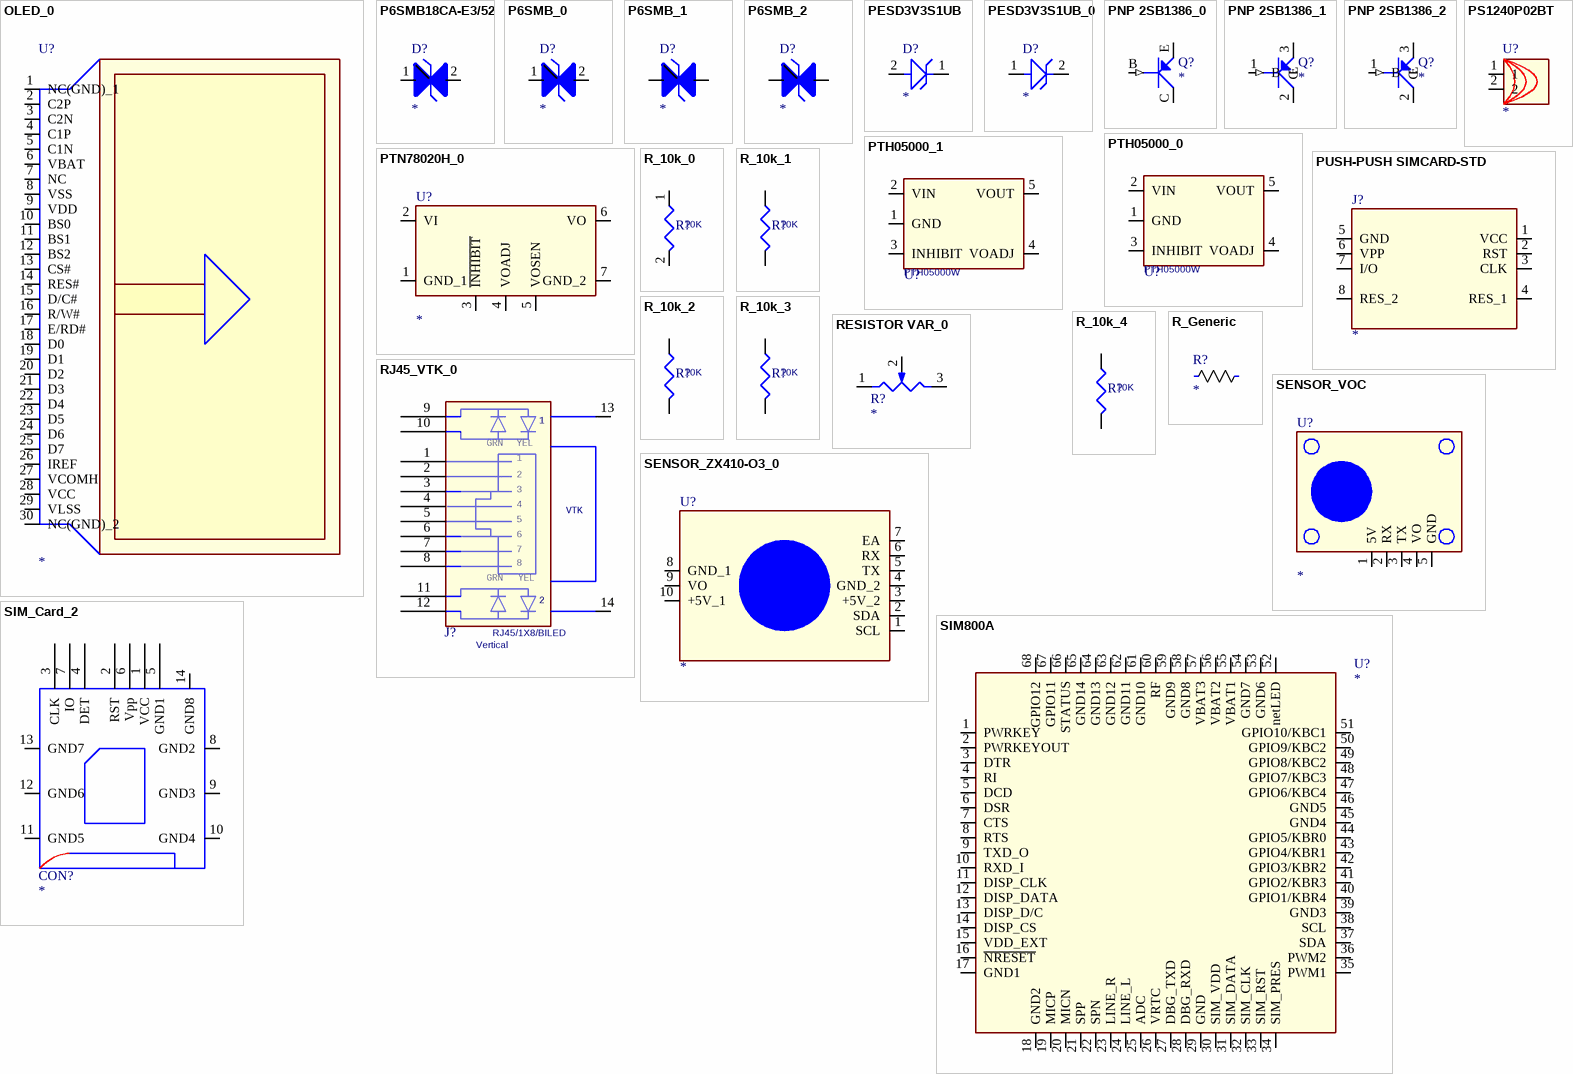
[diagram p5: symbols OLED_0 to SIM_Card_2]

## OLED_0
designator U?
footprint OLED_0r96
pins: 1 NC(GND)_1, 2 C2P, 3 C2N, 4 C1P, 5 C1N, 6 VBAT, 7 NC, 8 VSS, 9 VDD, 10 BS0, 11 BS1, 12 BS2, 13 CS#, 14 RES#, 15 D/C#, 16 R/W#, 17 E/RD#, 18 D0, 19 D1, 20 D2, 21 D3, 22 D4, 23 D5, 24 D6, 25 D7, 26 IREF, 27 VCOMH, 28 VCC, 29 VLSS, 30 NC(GND)_2

## P6SMB18CA-E3/52
designator D?
Corporation: VISHAY
footprint DO-214AA
pins: 1, 2

## P6SMB_0
designator D?
pins: 1, 2

## P6SMB_1
designator D?
pins: 1, 2

## P6SMB_2
designator D?
BI-DIRECTIONAL TVS
pins: 1, 2

## PESD3V3S1UB
designator D?
TVS; Corporation: NXP
footprint SOD523
pins: 1, 2

## PESD3V3S1UB_0
designator D?
TVS; Corporation: NXP
footprint SOD523
pins: 1, 2

## PNP 2SB1386_0
designator Q?
footprint SOT-89
pins: B base (in), C collector, E emitter

## PNP 2SB1386_1
designator Q?
footprint SOT-89
pins: 1 B (in), 2 C, 3 E

## PNP 2SB1386_2
designator Q?
footprint SOT-89
pins: 1 B (in), 2 C, 3 E

## PS1240P02BT
designator U?
pins: 1, 2

## PTH05000_0
designator U?, comment PTH05000W
6A,5V Input Non-Isolated Wide-Output Adjust Power Module; Corporation: TI
pins: 1 GND, 2 VIN, 3 INHIBIT, 4 VOADJ, 5 VOUT

## PTH05000_1
designator U?, comment PTH05000W
6A,5V Input Non-Isolated Wide-Output Adjust Power Module; Corporation: HYOC
pins: 1 GND, 2 VIN, 3 INHIBIT, 4 VOADJ, 5 VOUT

## PTN78020H_0
designator U?
footprint PTN78020H
pins: 1 GND_1, 2 VI, 3 ~{INHIBIT}, 4 VOADJ, 5 VOSEN, 6 VO, 7 GND_2

## PUSH-PUSH SIMCARD-STD
designator J?
STANDARD SIMCARD SOCKET
footprint SIMCARD-STD
pins: 1 VCC, 2 RST, 3 CLK, 4 RES_1, 5 GND, 6 VPP, 7 I/O, 8 RES_2

## R_10k_0
designator R?, comment 10K
footprint 0603
pins: 1, 2

## R_10k_1
designator R?, comment 10K
footprint 0603
pins: 1, 2

## R_10k_2
designator R?, comment 10K
Corporation: FH
footprint 0603
pins: 1, 2

## R_10k_3
designator R?, comment 10K
RES,1%,0.1 W,0603; Corporation: FH
footprint 0603
pins: 1, 2

## R_10k_4
designator R?, comment 10K
RES,1%,0.1 W,0603; Corporation: FH
footprint 0603
pins: 1, 2

## R_Generic
designator R?
pins: 1, 2

## RESISTOR VAR_0
designator R?
Corporation: VISHAY
pins: 1 A, 2 WIPER, 3 B

## RJ45_VTK_0
designator J?, comment RJ45/1X8/BILED  SHAPE: Vertical
MFGI 1#: Tyco: 1116075-8; MFG 2#: Amphenol: RJHS-538A; CETEC: 1116075-8   or  RJHS538A; MFG 3#: Xmultiple:  XRJ-S-01-B-0-8-F2
pins: 1 TXP1, 2 TXN1, 3 RXP1, 4, 5, 6 RXN1, 7, 8, 9 R1_YC_GA, 10 R1_YA_GC, 11 L1_YC_GA, 12 L1_YA_GC, 13 EG2, 14 EG1

## SENSOR_VOC
designator U?
SENSOR_VOC; Corporation: ECSENSE
footprint SENSOR_VOC
pins: 1 5V, 2 RX, 3 TX, 4 VO, 5 GND

## SENSOR_ZX410-O3_0
designator U?
SENSOR_ZX410-O3
footprint SENSOR_ZX410-O3
pins: 1 SCL, 2 SDA, 3 +5V_2, 4 GND_2, 5 TX, 6 RX, 7 EA, 8 GND_1, 9 VO, 10 +5V_1

## SIM800A
designator U?
footprint SIM800A
pins: 1 PWRKEY, 2 PWRKEYOUT, 3 DTR, 4 RI, 5 DCD, 6 DSR, 7 CTS, 8 RTS, 9 TXD_O, 10 RXD_I, 11 DISP_CLK, 12 DISP_DATA, 13 DISP_D/C, 14 DISP_CS, 15 VDD_EXT, 16 ~{NRESET}, 17 GND1, 18 GND2, 19 MICP, 20 MICN, 21 SPP, 22 SPN, 23 LINE_R, 24 LINE_L, 25 ADC, 26 VRTC, 27 DBG_TXD, 28 DBG_RXD, 29 GND, 30 SIM_VDD, 31 SIM_DATA, 32 SIM_CLK, 33 SIM_RST, 34 SIM_PRES, 35 PWM1, 36 PWM2, 37 SDA, 38 SCL, 39 GND3, 40 GPIO1/KBR4, 41 GPIO2/KBR3, 42 GPIO3/KBR2, 43 GPIO4/KBR1, 44 GPIO5/KBR0, 45 GND4, 46 GND5, 47 GPIO6/KBC4, 48 GPIO7/KBC3, 49 GPIO8/KBC2, 50 GPIO9/KBC2, 51 GPIO10/KBC1, 52 netLED, 53 GND6, 54 GND7, 55 VBAT1, 56 VBAT2, 57 VBAT3, 58 GND8, 59 GND9, 60 RF, 61 GND10, 62 GND11, 63 GND12, 64 GND13, 65 GND14, 66 STATUS, 67 GPIO11, 68 GPIO12

## SIM_Card_2
designator CON?
pins: 1 VCC, 2 RST, 3 CLK, 4 DET, 5 GND1, 6 Vpp, 7 IO, 8 GND2, 9 GND3, 10 GND4, 11 GND5, 12 GND6, 13 GND7, 14 GND8

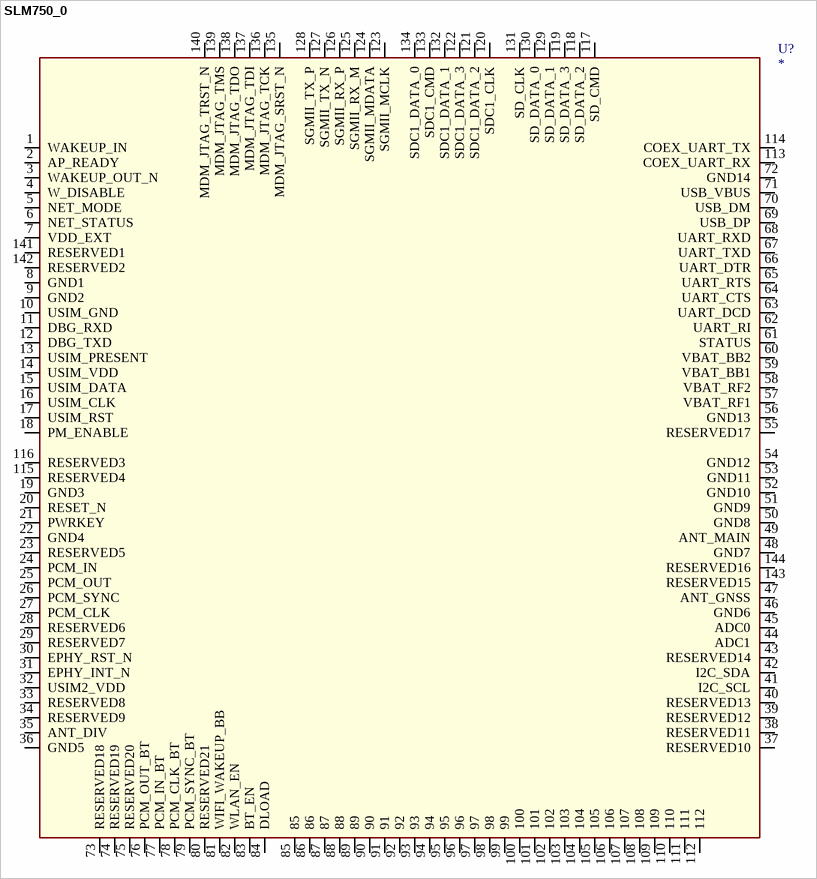
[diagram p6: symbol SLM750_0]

## SLM750_0
designator U?
4G LTE MODULE; Corporation: MEIG
footprint MEIG
pins: 1 WAKEUP_IN, 2 AP_READY, 3 WAKEUP_OUT_N, 4 W_DISABLE, 5 NET_MODE, 6 NET_STATUS, 7 VDD_EXT, 8 GND1, 9 GND2, 10 USIM_GND, 11 DBG_RXD, 12 DBG_TXD, 13 USIM_PRESENT, 14 USIM_VDD, 15 USIM_DATA, 16 USIM_CLK, 17 USIM_RST, 18 PM_ENABLE, 19 GND3, 20 RESET_N, 21 PWRKEY, 22 GND4, 23 RESERVED5, 24 PCM_IN, 25 PCM_OUT, 26 PCM_SYNC, 27 PCM_CLK, 28 RESERVED6, 29 RESERVED7, 30 EPHY_RST_N, 31 EPHY_INT_N, 32 USIM2_VDD, 33 RESERVED8, 34 RESERVED9, 35 ANT_DIV, 36 GND5, 37 RESERVED10, 38 RESERVED11, 39 RESERVED12, 40 RESERVED13, 41 I2C_SCL, 42 I2C_SDA, 43 RESERVED14, 44 ADC1, 45 ADC0, 46 GND6, 47 ANT_GNSS, 48 GND7, 49 ANT_MAIN, 50 GND8, 51 GND9, 52 GND10, 53 GND11, 54 GND12, 55 RESERVED17, 56 GND13, 57 VBAT_RF1, 58 VBAT_RF2, 59 VBAT_BB1, 60 VBAT_BB2, 61 STATUS, 62 UART_RI, 63 UART_DCD, 64 UART_CTS, 65 UART_RTS, 66 UART_DTR, 67 UART_TXD, 68 UART_RXD, 69 USB_DP, 70 USB_DM, 71 USB_VBUS, 72 GND14, 73 RESERVED18, 74 RESERVED19, 75 RESERVED20, 76 PCM_OUT_BT, 77 PCM_IN_BT, 78 PCM_CLK_BT, 79 PCM_SYNC_BT, 80 RESERVED21, 81 WIFI_WAKEUP_BB, 82 WLAN_EN, 83 BT_EN, 84 DLOAD, 85, 86, 87, 88, 89, 90, 91, 92, 93, 94, 95, 96, 97, 98, 99, 100, 101, 102, 103, 104, 105, 106, 107, 108, 109, 110, 111, 112, 113 COEX_UART_RX, 114 COEX_UART_TX, 115 RESERVED4, 116 RESERVED3, 117 SD_CMD, 118 SD_DATA_2, 119 SD_DATA_3, 120 SDC1_CLK, 121 SDC1_DATA_2, 122 SDC1_DATA_3, 123 SGMII_MCLK, 124 SGMII_MDATA, 125 SGMII_RX_M, 126 SGMII_RX_P, 127 SGMII_TX_N, 128 SGMII_TX_P, 129 SD_DATA_1, 130 SD_DATA_0, 131 SD_CLK, 132 SDC1_DATA_1, 133 SDC1_CMD, 134 SDC1_DATA_0, 135 MDM_JTAG_SRST_N, 136 MDM_JTAG_TCK, 137 MDM_JTAG_TDI, 138 MDM_JTAG_TDO, 139 MDM_JTAG_TMS, 140 MDM_JTAG_TRST_N, 141 RESERVED1, 142 RESERVED2, 143 RESERVED15, 144 RESERVED16

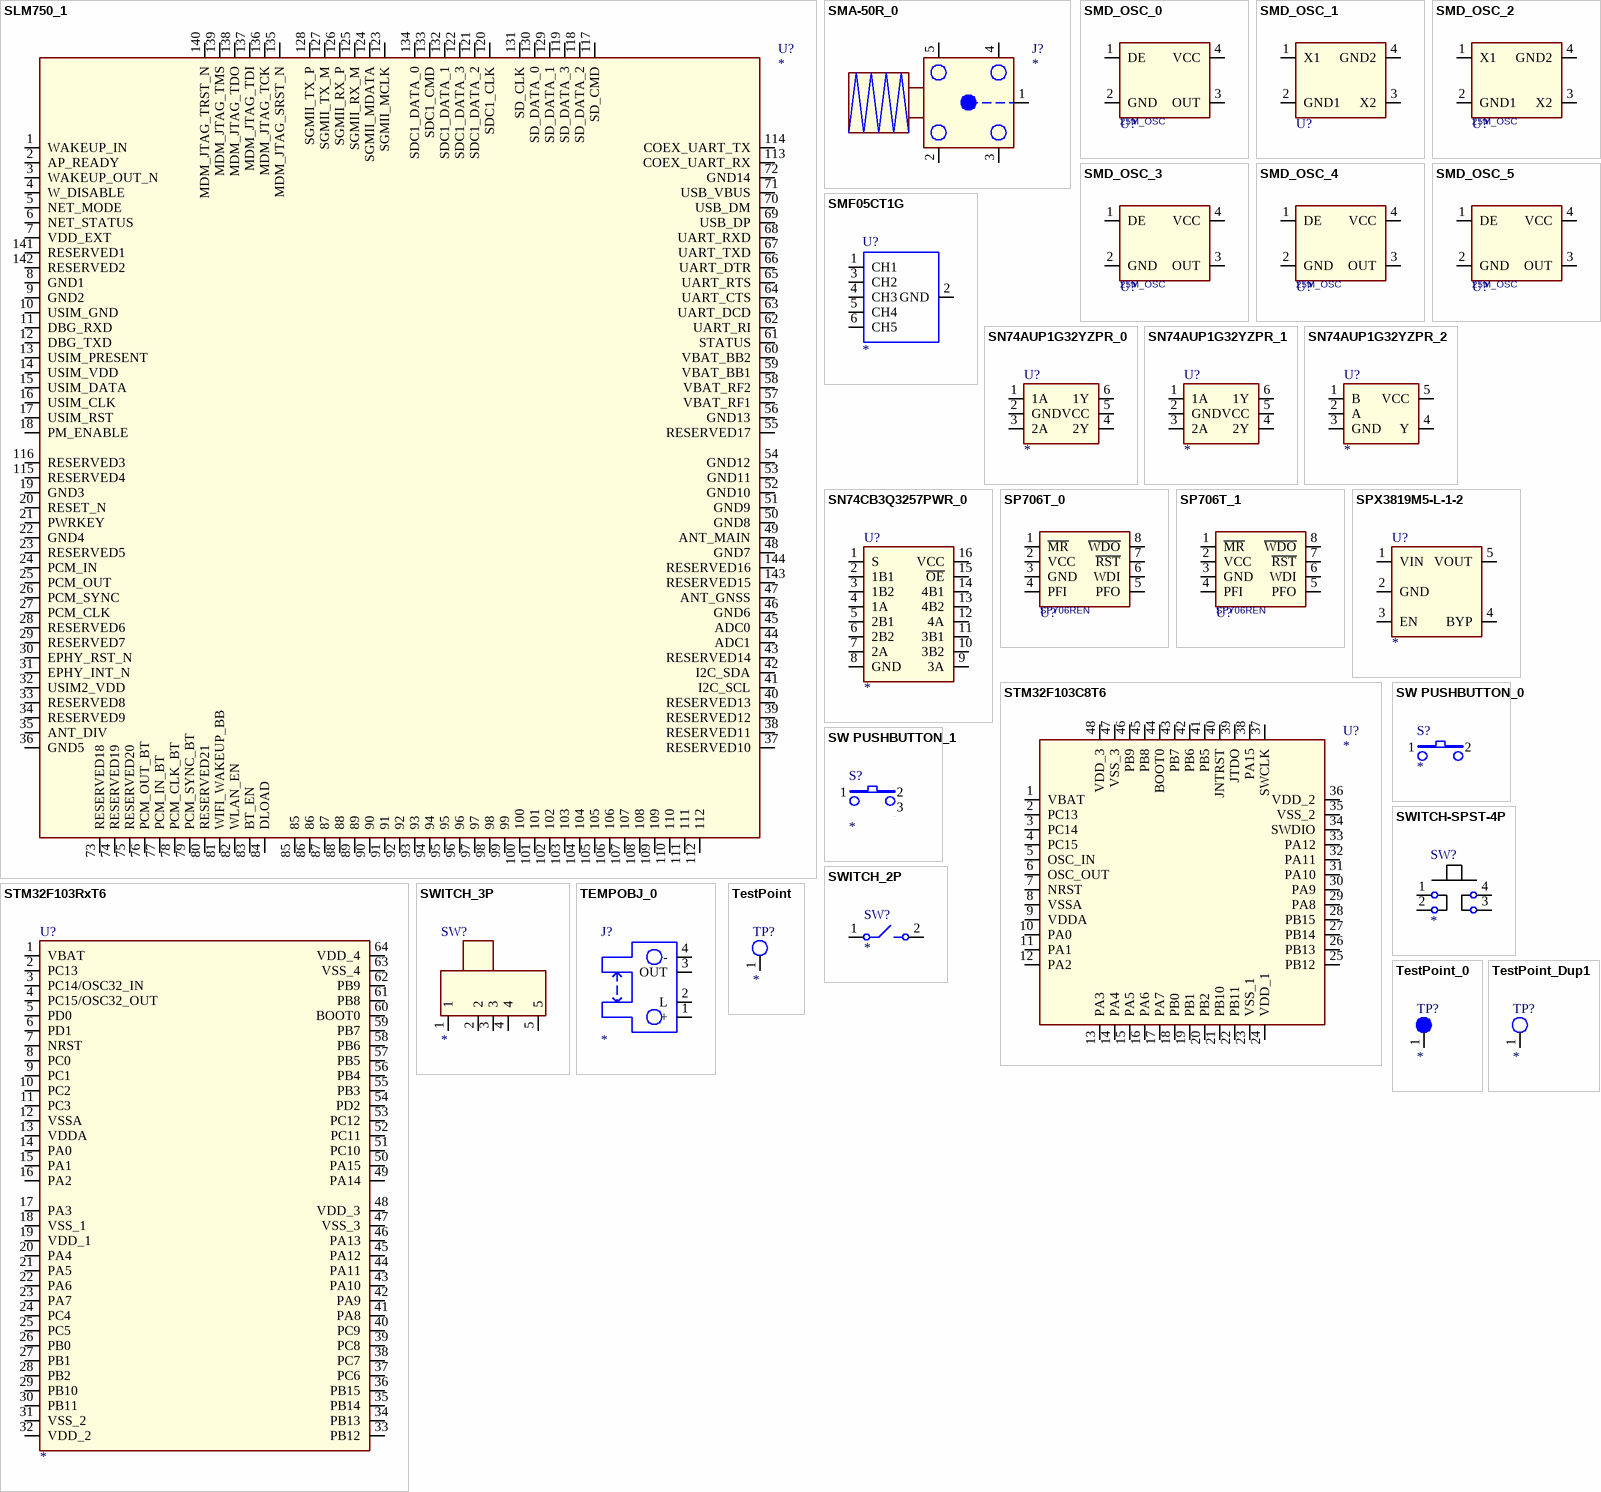
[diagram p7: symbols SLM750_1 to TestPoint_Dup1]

## SLM750_1
designator U?
4G LTE MODULE; Corporation: MEIG
footprint MEIG
pins: 1 WAKEUP_IN, 2 AP_READY, 3 WAKEUP_OUT_N, 4 W_DISABLE, 5 NET_MODE, 6 NET_STATUS, 7 VDD_EXT, 8 GND1, 9 GND2, 10 USIM_GND, 11 DBG_RXD, 12 DBG_TXD, 13 USIM_PRESENT, 14 USIM_VDD, 15 USIM_DATA, 16 USIM_CLK, 17 USIM_RST, 18 PM_ENABLE, 19 GND3, 20 RESET_N, 21 PWRKEY, 22 GND4, 23 RESERVED5, 24 PCM_IN, 25 PCM_OUT, 26 PCM_SYNC, 27 PCM_CLK, 28 RESERVED6, 29 RESERVED7, 30 EPHY_RST_N, 31 EPHY_INT_N, 32 USIM2_VDD, 33 RESERVED8, 34 RESERVED9, 35 ANT_DIV, 36 GND5, 37 RESERVED10, 38 RESERVED11, 39 RESERVED12, 40 RESERVED13, 41 I2C_SCL, 42 I2C_SDA, 43 RESERVED14, 44 ADC1, 45 ADC0, 46 GND6, 47 ANT_GNSS, 48 GND7, 49 ANT_MAIN, 50 GND8, 51 GND9, 52 GND10, 53 GND11, 54 GND12, 55 RESERVED17, 56 GND13, 57 VBAT_RF1, 58 VBAT_RF2, 59 VBAT_BB1, 60 VBAT_BB2, 61 STATUS, 62 UART_RI, 63 UART_DCD, 64 UART_CTS, 65 UART_RTS, 66 UART_DTR, 67 UART_TXD, 68 UART_RXD, 69 USB_DP, 70 USB_DM, 71 USB_VBUS, 72 GND14, 73 RESERVED18, 74 RESERVED19, 75 RESERVED20, 76 PCM_OUT_BT, 77 PCM_IN_BT, 78 PCM_CLK_BT, 79 PCM_SYNC_BT, 80 RESERVED21, 81 WIFI_WAKEUP_BB, 82 WLAN_EN, 83 BT_EN, 84 DLOAD, 85, 86, 87, 88, 89, 90, 91, 92, 93, 94, 95, 96, 97, 98, 99, 100, 101, 102, 103, 104, 105, 106, 107, 108, 109, 110, 111, 112, 113 COEX_UART_RX, 114 COEX_UART_TX, 115 RESERVED4, 116 RESERVED3, 117 SD_CMD, 118 SD_DATA_2, 119 SD_DATA_3, 120 SDC1_CLK, 121 SDC1_DATA_2, 122 SDC1_DATA_3, 123 SGMII_MCLK, 124 SGMII_MDATA, 125 SGMII_RX_M, 126 SGMII_RX_P, 127 SGMII_TX_M, 128 SGMII_TX_P, 129 SD_DATA_1, 130 SD_DATA_0, 131 SD_CLK, 132 SDC1_DATA_1, 133 SDC1_CMD, 134 SDC1_DATA_0, 135 MDM_JTAG_SRST_N, 136 MDM_JTAG_TCK, 137 MDM_JTAG_TDI, 138 MDM_JTAG_TDO, 139 MDM_JTAG_TMS, 140 MDM_JTAG_TRST_N, 141 RESERVED1, 142 RESERVED2, 143 RESERVED15, 144 RESERVED16

## SMA-50R_0
designator J?
footprint SMA-50R
pins: 1, 2, 3, 4, 5

## SMD_OSC_0
designator U?, comment 25M_OSC
footprint XTAL1
pins: 1 DE, 2 GND, 3 OUT, 4 VCC

## SMD_OSC_1
designator U?, comment 25M_OSC  (value not drawn)
footprint XTAL1
pins: 1 X1, 2 GND1, 3 X2, 4 GND2

## SMD_OSC_2
designator U?, comment 25M_OSC
footprint XTAL1
pins: 1 X1, 2 GND1, 3 X2, 4 GND2

## SMD_OSC_3
designator U?, comment 25M_OSC
XTAL,25MHz,+-20PPM,20pF; Corporation: EPSON
footprint XTAL1
pins: 1 DE, 2 GND, 3 OUT, 4 VCC

## SMD_OSC_4
designator U?, comment 25M_OSC
XTAL,Oscillator,25MHz,+-20PPM,20pF; Corporation: EPSON
footprint XTAL1
pins: 1 DE, 2 GND, 3 OUT, 4 VCC

## SMD_OSC_5
designator U?, comment 25M_OSC
XTAL,Oscillator,25MHz,+-50PPM; Corporation: EPSON
footprint XTAL1
pins: 1 DE, 2 GND, 3 OUT, 4 VCC

## SMF05CT1G
designator U?
5-Line TVS Array; Corporation: ON
pins: 1 CH1, 2 GND, 3 CH2, 4 CH3, 5 CH4, 6 CH5

## SN74AUP1G32YZPR_0
designator U?
pins: 1 1A, 2 GND, 3 2A, 4 2Y, 5 VCC, 6 1Y

## SN74AUP1G32YZPR_1
designator U?
Dual Schmitt-Trigger Inverter; Corporation: TI
pins: 1 1A, 2 GND, 3 2A, 4 2Y, 5 VCC, 6 1Y

## SN74AUP1G32YZPR_2
designator U?
Single 2-Input Positive-AND Gate; Corporation: TI
pins: 1 B, 2 A, 3 GND, 4 Y, 5 VCC

## SN74CB3Q3257PWR_0
designator U?
4-Bit 1-of-2 FET Multiplexer; Corporation: TI
footprint ssop16
pins: 1 S, 2 1B1, 3 1B2, 4 1A, 5 2B1, 6 2B2, 7 2A, 8 GND, 9 3A, 10 3B2, 11 3B1, 12 4A, 13 4B2, 14 4B1, 15 ~{OE}, 16 VCC

## SP706T_0
designator U?, comment SP706REN
footprint SO8
pins: 1 ~{MR}, 2 VCC, 3 GND, 4 PFI, 5 PFO, 6 WDI, 7 ~{RST}, 8 ~{WDO}

## SP706T_1
designator U?, comment SP706REN
Microprocessor?Supervisory?Circuits; Corporation: SIPEX
footprint SO8
pins: 1 ~{MR}, 2 VCC, 3 GND, 4 PFI, 5 PFO, 6 WDI, 7 ~{RST}, 8 ~{WDO}

## SPX3819M5-L-1-2
designator U?
Corporation: SIPEX
footprint SOT23-5
pins: 1 VIN, 2 GND, 3 EN, 4 BYP, 5 VOUT

## STM32F103C8T6
designator U?
Cortex-M3 MCU; Corporation: ST
footprint LQFP-48
pins: 1 VBAT, 2 PC13, 3 PC14, 4 PC15, 5 OSC_IN, 6 OSC_OUT, 7 NRST, 8 VSSA, 9 VDDA, 10 PA0, 11 PA1, 12 PA2, 13 PA3, 14 PA4, 15 PA5, 16 PA6, 17 PA7, 18 PB0, 19 PB1, 20 PB2, 21 PB10, 22 PB11, 23 VSS_1, 24 VDD_1, 25 PB12, 26 PB13, 27 PB14, 28 PB15, 29 PA8, 30 PA9, 31 PA10, 32 PA11, 33 PA12, 34 SWDIO, 35 VSS_2, 36 VDD_2, 37 SWCLK, 38 PA15, 39 JTDO, 40 JNTRST, 41 PB5, 42 PB6, 43 PB7, 44 BOOT0, 45 PB8, 46 PB9, 47 VSS_3, 48 VDD_3

## STM32F103RxT6
designator U?
ST Cortex-m3 MCU
footprint QFP-64
pins: 1 VBAT, 2 PC13, 3 PC14/OSC32_IN, 4 PC15/OSC32_OUT, 5 PD0, 6 PD1, 7 NRST, 8 PC0, 9 PC1, 10 PC2, 11 PC3, 12 VSSA, 13 VDDA, 14 PA0, 15 PA1, 16 PA2, 17 PA3, 18 VSS_1, 19 VDD_1, 20 PA4, 21 PA5, 22 PA6, 23 PA7, 24 PC4, 25 PC5, 26 PB0, 27 PB1, 28 PB2, 29 PB10, 30 PB11, 31 VSS_2, 32 VDD_2, 33 PB12, 34 PB13, 35 PB14, 36 PB15, 37 PC6, 38 PC7, 39 PC8, 40 PC9, 41 PA8, 42 PA9, 43 PA10, 44 PA11, 45 PA12, 46 PA13, 47 VSS_3, 48 VDD_3, 49 PA14, 50 PA15, 51 PC10, 52 PC11, 53 PC12, 54 PD2, 55 PB3, 56 PB4, 57 PB5, 58 PB6, 59 PB7, 60 BOOT0, 61 PB8, 62 PB9, 63 VSS_4, 64 VDD_4

## SW PUSHBUTTON_0
designator S?
pins: 1, 2

## SW PUSHBUTTON_1
designator S?
pins: 1, 2, 3

## SWITCH-SPST-4P
designator SW?
footprint SPST
pins: 1, 2, 3, 4

## SWITCH_2P
designator SW?
pins: 1, 2

## SWITCH_3P
designator SW?
footprint SWITCH_3P
pins: 1, 2, 3, 4, 5

## TEMPOBJ_0
designator J?
Corporation: OMRON
footprint EE-SX670
pins: 1 +, 2 L, 3 OUT, 4 -

## TestPoint
designator TP?
footprint TP-0R75
pins: 1

## TestPoint_0
designator TP?
footprint TP-0R75
pins: 1

## TestPoint_Dup1
designator TP?
footprint TestPoint
pins: 1

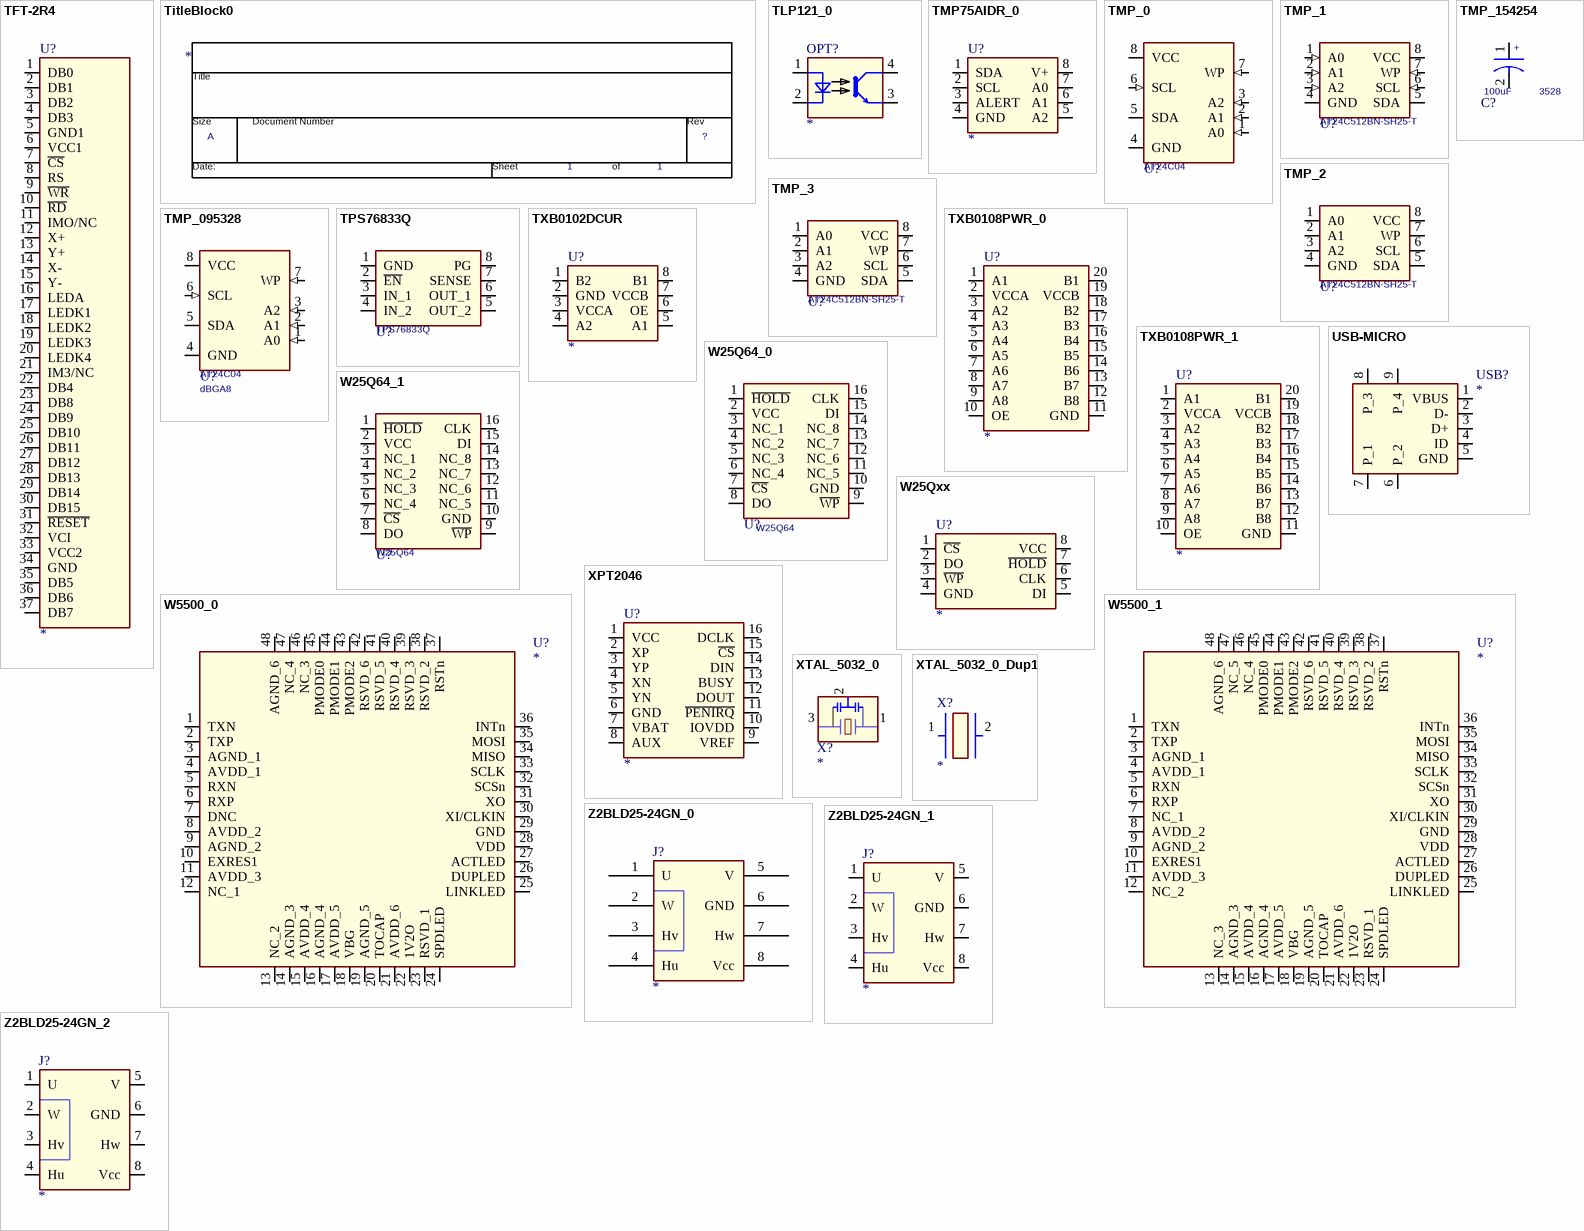
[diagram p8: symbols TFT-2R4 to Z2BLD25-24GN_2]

## TFT-2R4
designator U?
ILI9341 2.4 TFT; Corporation: ILI
footprint TFT-2R4
pins: 1 DB0, 2 DB1, 3 DB2, 4 DB3, 5 GND1, 6 VCC1, 7 ~{CS}, 8 RS, 9 ~{WR}, 10 ~{RD}, 11 IMO/NC, 12 X+, 13 Y+, 14 X-, 15 Y-, 16 LEDA, 17 LEDK1, 18 LEDK2, 19 LEDK3, 20 LEDK4, 21 IM3/NC, 22 DB4, 23 DB8, 24 DB9, 25 DB10, 26 DB11, 27 DB12, 28 DB13, 29 DB14, 30 DB15, 31 ~{RESET}, 32 VCI, 33 VCC2, 34 GND, 35 DB5, 36 DB6, 37 DB7

## TitleBlock0
designator *  Page Size: A  Page Number: 1  (graphical)

## TLP121_0
designator OPT?
Corporation: TOSHIBA
footprint TLP121
pins: 1 A, 2 K, 3 C, 4 E

## TMP75AIDR_0
designator U?
Temperature Sensor; Corporation: TI
footprint SOIC8
pins: 1 SDA, 2 SCL, 3 ALERT, 4 GND, 5 A2, 6 A1, 7 A0, 8 V+

## TMP_0
designator U?, comment AT24C04
EEPROM; Corporation: ATMEL; EPI#: P11100000000005; MFGI 2#: NA; MFGI 1#: ATM: AT24C04U3-10UU-1.8; GRN: HR
footprint BGA100-50P2X4-8A
pins: 1 A0 (in), 2 A1 (in), 3 A2 (in), 4 GND (power), 5 SDA (oc), 6 SCL (in), 7 WP (in), 8 VCC (power)

## TMP_1
designator U?, comment AT24C512BN-SH25-T
Two-wire?Serial EEPROM 512K Bits; Corporation: ATMEL; EPI#: P11100000000005; MFGI 2#: NA; MFGI 1#: ATM: AT24C04U3-10UU-1.8; GRN: HR
footprint BGA100-50P2X4-8A
pins: 1 A0 (in), 2 A1 (in), 3 A2 (in), 4 GND (power), 5 SDA (oc), 6 SCL (in), 7 WP (in), 8 VCC (power)

## TMP_2
designator U?, comment AT24C512BN-SH25-T
Two-wire?Serial EEPROM 512K Bits; Corporation: ATMEL; EPI#: P11100000000005; MFGI 2#: NA; MFGI 1#: ATM: AT24C04U3-10UU-1.8; GRN: HR
footprint BGA100-50P2X4-8A
pins: 1 A0, 2 A1, 3 A2, 4 GND, 5 SDA, 6 SCL, 7 WP, 8 VCC

## TMP_3
designator U?, comment AT24C512BN-SH25-T
Two-wire Serial EEPROM 512K Bit; Corporation: ATMEL; EPI#: P11100000000005; MFGI 2#: NA; MFGI 1#: ATM: AT24C04U3-10UU-1.8; GRN: HR
footprint BGA100-50P2X4-8A
pins: 1 A0, 2 A1, 3 A2, 4 GND, 5 SDA, 6 SCL, 7 WP, 8 VCC

## TMP_095328
designator U?, comment AT24C04  Shape: dBGA8
GRN: HR; EP#: P11100000000005; MFG 2#: NA; MFG 1#: ATM: AT24C04U3-10UU-1.8
footprint BGA100-50P2X4-8A
pins: 1 A0 (in), 2 A1 (in), 3 A2 (in), 4 GND (power), 5 SDA (oc), 6 SCL (in), 7 WP (in), 8 VCC (power)

## TMP_154254
designator C?, comment 100uF  Shape: 3528
Cap,Tan,47uF/16V,3528; EPI#: P10100000000041; MFG 2#: KEM: T494B107K006ATH; MFG 1#: AVX: TPSB107K006R; Type: LESR; GRN: LHR; Corporation: AVX
footprint CT_3528_IPC
pins: 1, 2
1 alternate drawing of the same symbol

## TPS76833Q
designator U?
Corporation: TI
footprint SOIC8
pins: 1 GND (power), 2 ~{EN}, 3 IN_1, 4 IN_2, 5 OUT_2, 6 OUT_1, 7 SENSE, 8 PG

## TXB0102DCUR
designator U?
2-Bit Bidirectional Voltage-Level Translator; Corporation: TI
footprint VSSOP8
pins: 1 B2, 2 GND, 3 VCCA, 4 A2, 5 A1, 6 OE, 7 VCCB, 8 B1

## TXB0108PWR_0
designator U?
Corporation: TI
pins: 1 A1, 2 VCCA, 3 A2, 4 A3, 5 A4, 6 A5, 7 A6, 8 A7, 9 A8, 10 OE, 11 GND, 12 B8, 13 B7, 14 B6, 15 B5, 16 B4, 17 B3, 18 B2, 19 VCCB, 20 B1

## TXB0108PWR_1
designator U?
8-Bit Bidirectional Voltage-Level Translator; Corporation: TI
pins: 1 A1, 2 VCCA, 3 A2, 4 A3, 5 A4, 6 A5, 7 A6, 8 A7, 9 A8, 10 OE, 11 GND, 12 B8, 13 B7, 14 B6, 15 B5, 16 B4, 17 B3, 18 B2, 19 VCCB, 20 B1

## USB-MICRO
designator USB?
footprint MICROUSB
pins: 1 VBUS, 2 D-, 3 D+, 4 ID, 5 GND, 6 P_2, 7 P_1, 8 P_3, 9 P_4

## W25Q64_0
designator U?, comment W25Q64
pins: 1 ~{HOLD}, 2 VCC, 3 NC_1, 4 NC_2, 5 NC_3, 6 NC_4, 7 ~{CS}, 8 DO, 9 ~{WP}, 10 GND (power), 11 NC_5, 12 NC_6, 13 NC_7, 14 NC_8, 15 DI, 16 CLK

## W25Q64_1
designator U?, comment W25Q64
128M-BIT SPI FLASH; Corporation: WINBOND
pins: 1 ~{HOLD}, 2 VCC, 3 NC_1, 4 NC_2, 5 NC_3, 6 NC_4, 7 ~{CS}, 8 DO, 9 ~{WP}, 10 GND (power), 11 NC_5, 12 NC_6, 13 NC_7, 14 NC_8, 15 DI, 16 CLK

## W25Qxx
designator U?
footprint SO-8-W
pins: 1 ~{CS}, 2 DO, 3 ~{WP}, 4 GND, 5 DI, 6 CLK, 7 ~{HOLD}, 8 VCC

## W5500_0
designator U?
footprint LQFP-48
pins: 1 TXN, 2 TXP, 3 AGND_1, 4 AVDD_1, 5 RXN, 6 RXP, 7 DNC, 8 AVDD_2, 9 AGND_2, 10 EXRES1, 11 AVDD_3, 12 NC_1, 13 NC_2, 14 AGND_3, 15 AVDD_4, 16 AGND_4, 17 AVDD_5, 18 VBG, 19 AGND_5, 20 TOCAP, 21 AVDD_6, 22 1V2O, 23 RSVD_1, 24 SPDLED, 25 LINKLED, 26 DUPLED, 27 ACTLED, 28 VDD, 29 GND, 30 XI/CLKIN, 31 XO, 32 SCSn, 33 SCLK, 34 MISO, 35 MOSI, 36 INTn, 37 RSTn, 38 RSVD_2, 39 RSVD_3, 40 RSVD_4, 41 RSVD_5, 42 RSVD_6, 43 PMODE2, 44 PMODE1, 45 PMODE0, 46 NC_3, 47 NC_4, 48 AGND_6

## W5500_1
designator U?
footprint LQFP-48
pins: 1 TXN, 2 TXP, 3 AGND_1, 4 AVDD_1, 5 RXN, 6 RXP, 7 NC_1, 8 AVDD_2, 9 AGND_2, 10 EXRES1, 11 AVDD_3, 12 NC_2, 13 NC_3, 14 AGND_3, 15 AVDD_4, 16 AGND_4, 17 AVDD_5, 18 VBG, 19 AGND_5, 20 TOCAP, 21 AVDD_6, 22 1V2O, 23 RSVD_1, 24 SPDLED, 25 LINKLED, 26 DUPLED, 27 ACTLED, 28 VDD, 29 GND, 30 XI/CLKIN, 31 XO, 32 SCSn, 33 SCLK, 34 MISO, 35 MOSI, 36 INTn, 37 RSTn, 38 RSVD_2, 39 RSVD_3, 40 RSVD_4, 41 RSVD_5, 42 RSVD_6, 43 PMODE2, 44 PMODE1, 45 PMODE0, 46 NC_4, 47 NC_5, 48 AGND_6

## XPT2046
designator U?
Touch Screen Controller; Corporation: XPT
footprint TSSOP-16
pins: 1 VCC, 2 XP, 3 YP, 4 XN, 5 YN, 6 GND, 7 VBAT, 8 AUX, 9 VREF, 10 IOVDD, 11 ~{PENIRQ}, 12 DOUT, 13 BUSY, 14 DIN, 15 ~{CS}, 16 DCLK

## XTAL_5032_0
designator X?
Corporation: muRata
footprint XTAL_5032
pins: 1, 2, 3

## XTAL_5032_0_Dup1
designator X?
footprint XTAL_5032
pins: 1, 2

## Z2BLD25-24GN_0
designator J?
pins: 1 U, 2 W, 3 Hv, 4 Hu, 5 V, 6 GND, 7 Hw, 8 Vcc

## Z2BLD25-24GN_1
designator J?
pins: 1 U, 2 W, 3 Hv, 4 Hu, 5 V, 6 GND, 7 Hw, 8 Vcc

## Z2BLD25-24GN_2
designator J?
Corporation: MOLEX
pins: 1 U, 2 W, 3 Hv, 4 Hu, 5 V, 6 GND, 7 Hw, 8 Vcc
